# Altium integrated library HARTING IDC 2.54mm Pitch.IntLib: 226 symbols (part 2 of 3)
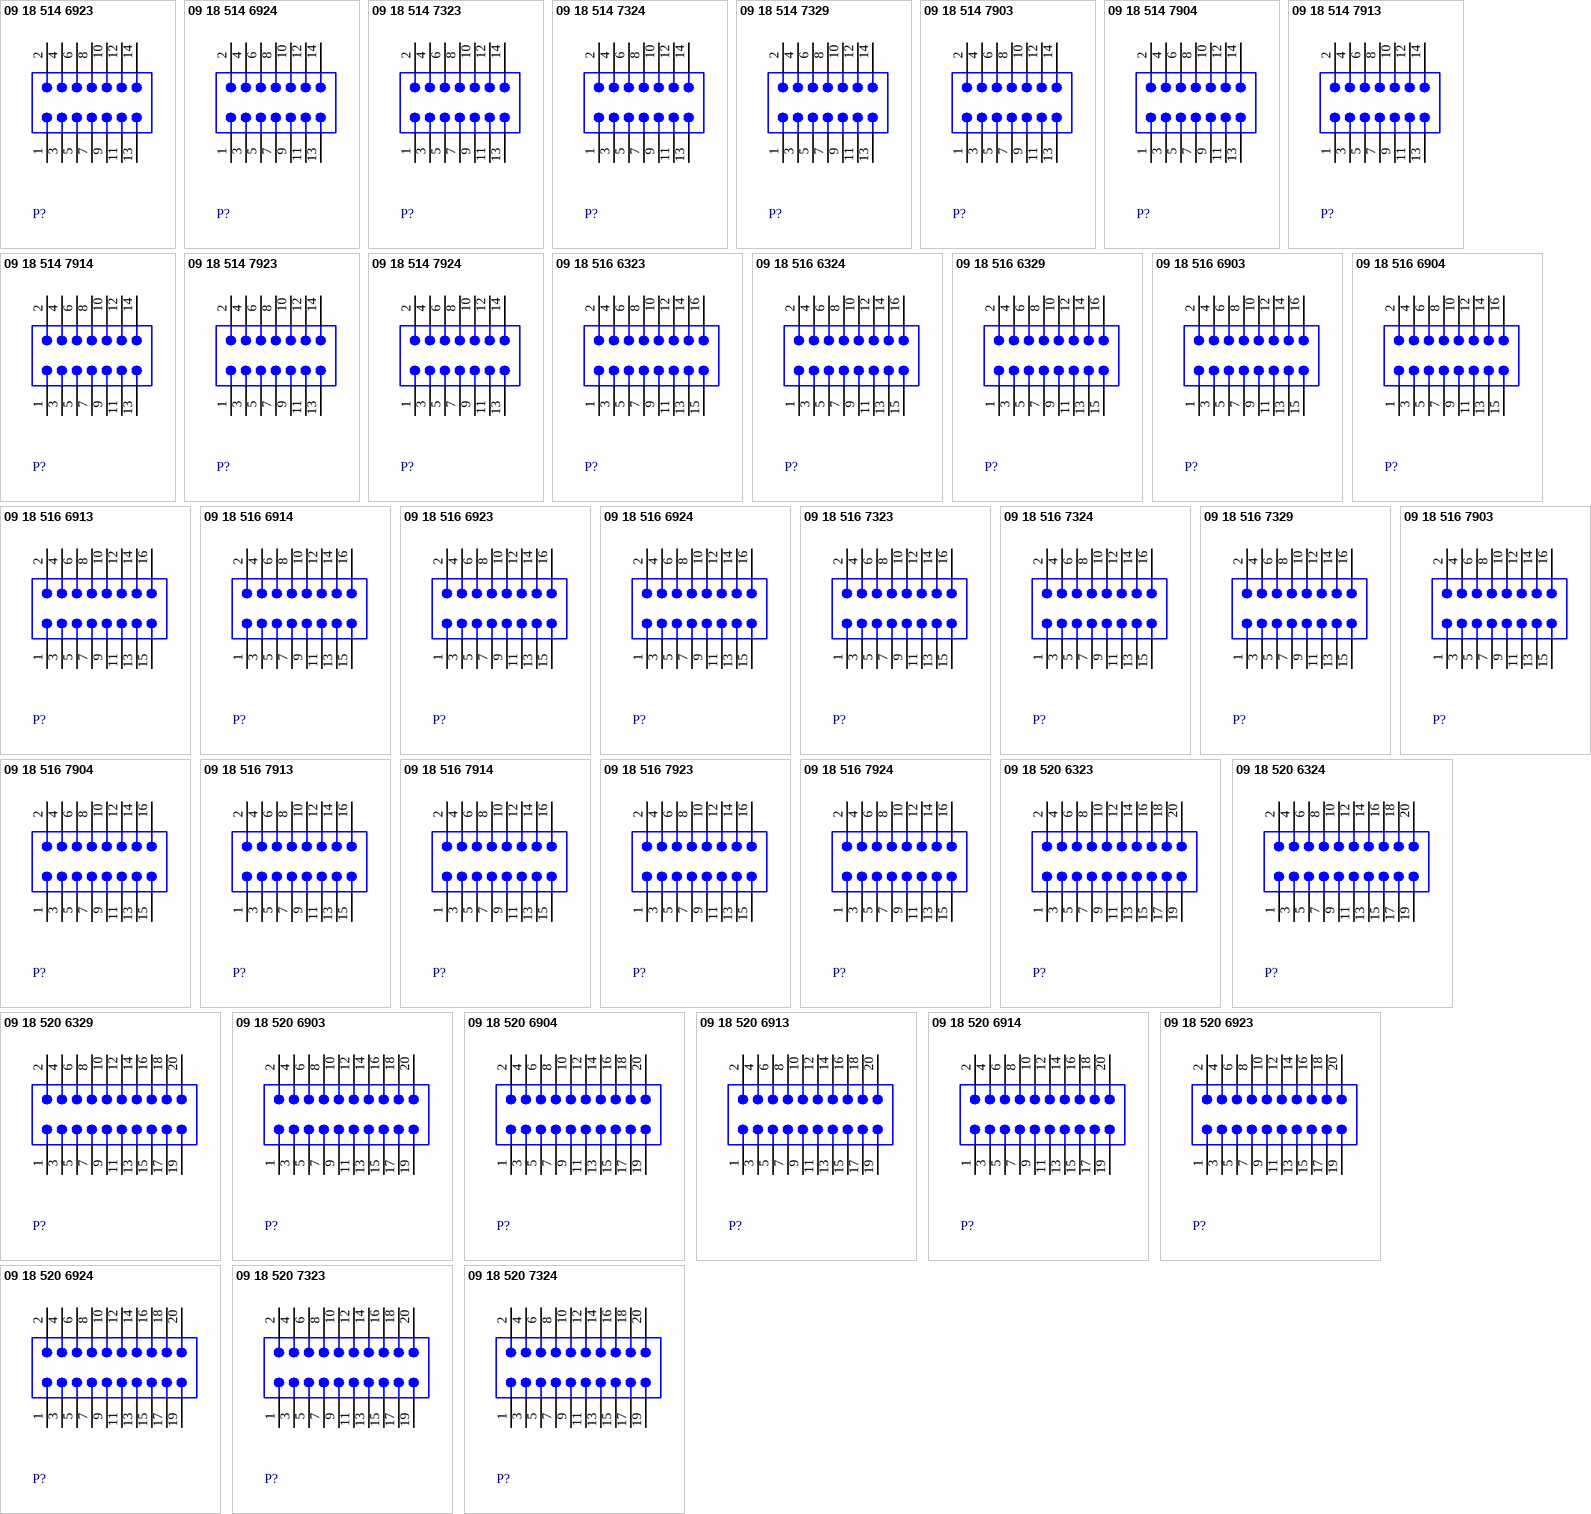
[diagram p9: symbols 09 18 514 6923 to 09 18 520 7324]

## 09 18 520 7323
designator P?
Flat Cable Connector (IDC), Low-Profile Male Header, Angled Solder Pin, 20 Contacts, Performance Level 3; PCB_Layout: Complies with manufacturer's recommendation.; DrillSize: Corresponds to nominal value.
footprint 918520x323 (Connector; IDC, Low Profile Male Header, Thru-Hole; 20 Position; Right Angle; Pitch 2.54 mm; Body 33.02 x 8.9 x 9.2 mm (LxWxH))
pins: 1, 2, 3, 4, 5, 6, 7, 8, 9, 10, 11, 12, 13, 14, 15, 16, 17, 18, 19, 20

## 09 18 520 7324
designator P?
Flat Cable Connector (IDC), Low-Profile Male Header, Straight Solder Pin, 20 Contacts, Performance Level 3; PCB_Layout: Complies with manufacturer's recommendation.; DrillSize: Corresponds to nominal value.
footprint 918520x324 (Connector; IDC, Low Profile Male Header, Thru-Hole; 20 Position; Vertical; Pitch 2.54 mm; Body 33.02 x 9.2 x 9.45 mm (LxWxH))
pins: 1, 2, 3, 4, 5, 6, 7, 8, 9, 10, 11, 12, 13, 14, 15, 16, 17, 18, 19, 20

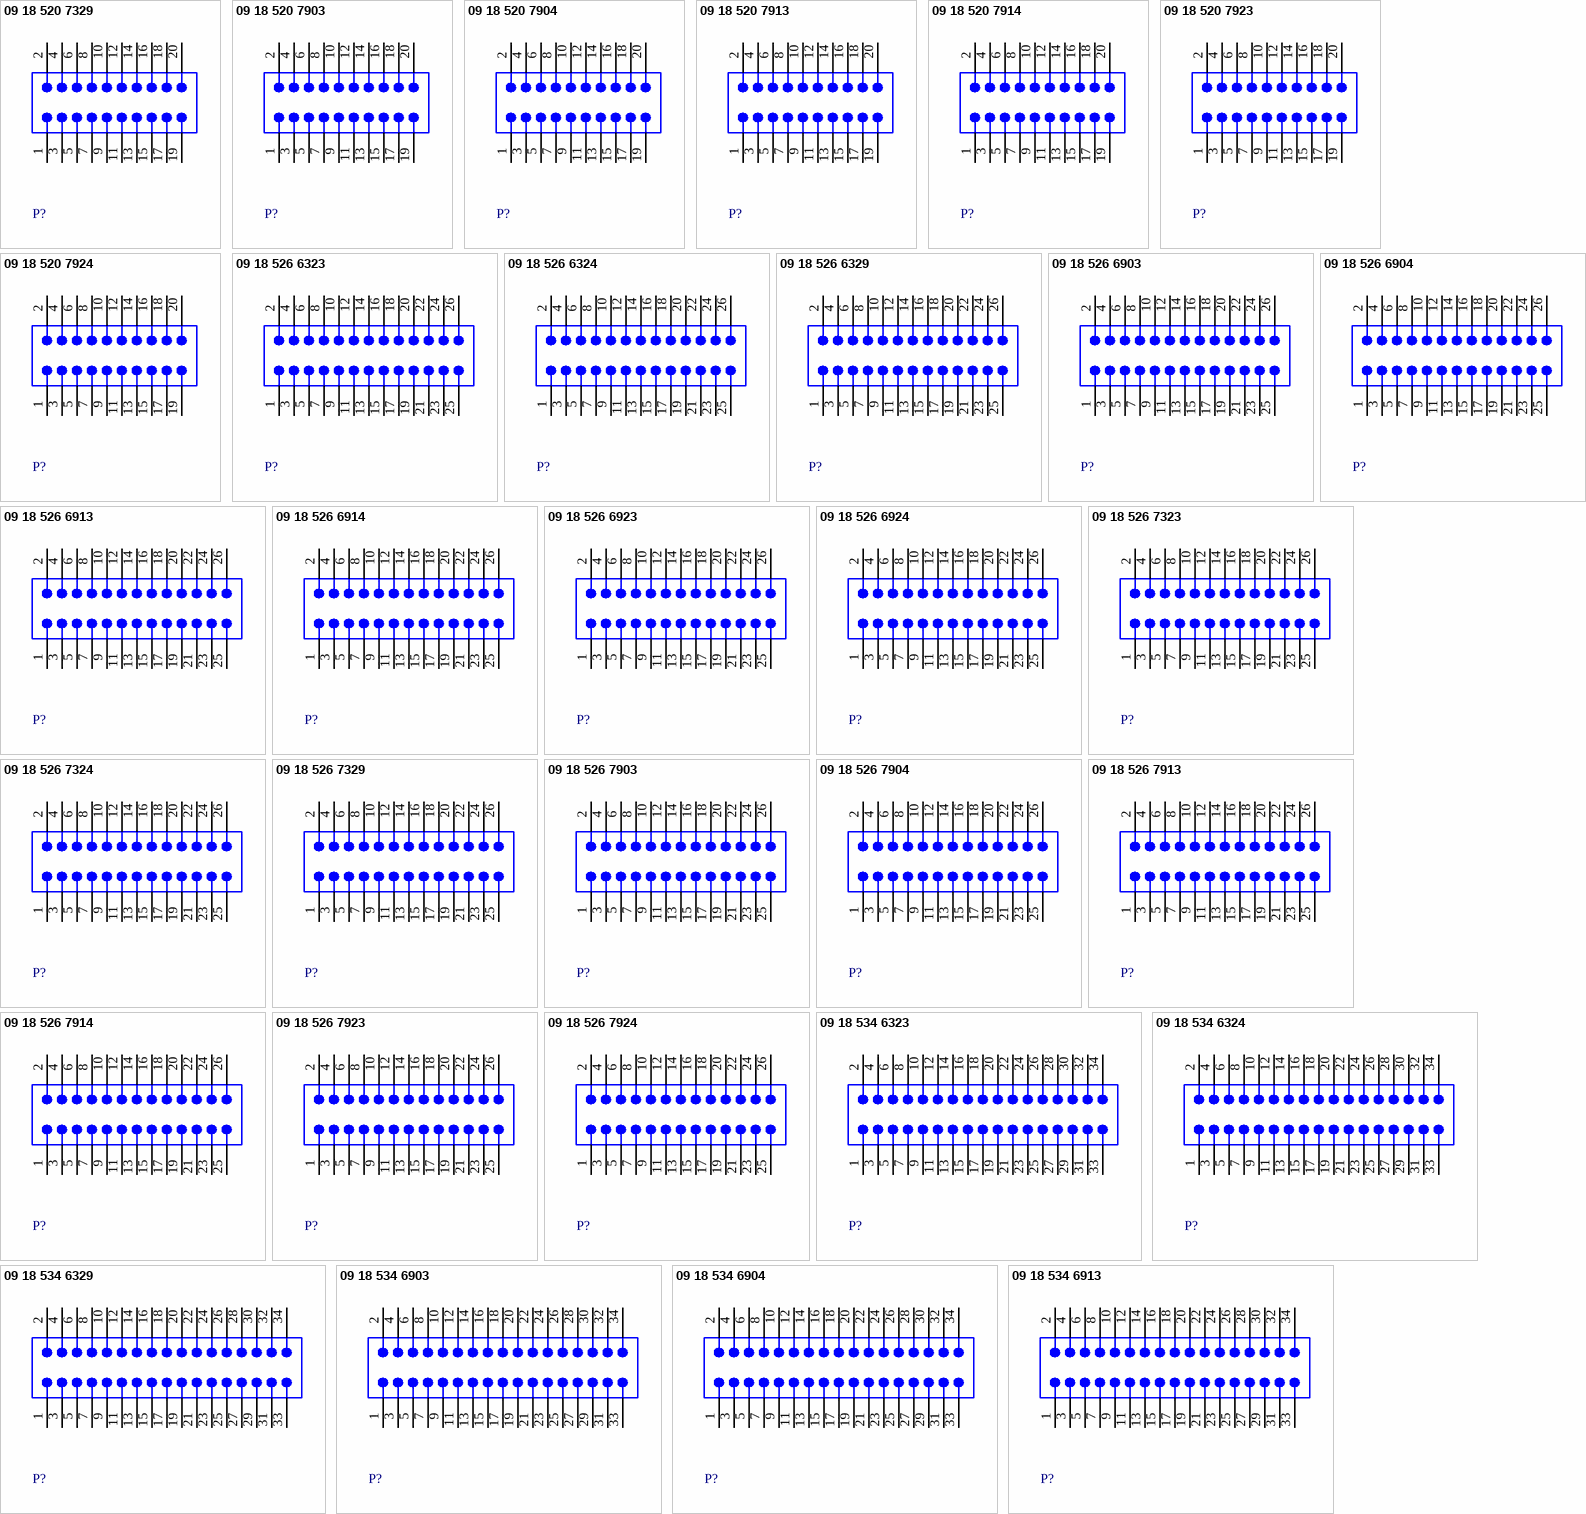
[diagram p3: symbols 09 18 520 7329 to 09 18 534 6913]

## 09 18 520 7329
designator P?
Flat Cable Connector (IDC), Standard Male Header, Straight Press-in Pin, 20 Contacts, Performance Level 3; PCB_Layout: Complies with manufacturer's recommendation.; DrillSize: Corresponds to nominal value.
footprint 918520x329 (Connector; IDC, Straight Press-in Pin, Thru-Hole; 20 Position; Vertical; Pitch 2.54 mm; Body 33.02 x 9.2 x 9.45 mm (LxWxH))
pins: 1, 2, 3, 4, 5, 6, 7, 8, 9, 10, 11, 12, 13, 14, 15, 16, 17, 18, 19, 20

## 09 18 520 7903
designator P?
Flat Cable Connector (IDC), Standard Male Header, Angled Solder Pin, 20 Contacts, Long Levers, Performance Level 3; PCB_Layout: Complies with manufacturer's recommendation.; DrillSize: Corresponds to nominal value.
footprint 918520x903 (Connector; IDC, Thru-Hole; 20 Position; Right Angle; Pitch 2.54 mm; Body 45.00 x 8.5 x 25.75 mm (LxHxW), Locking levers)
pins: 1, 2, 3, 4, 5, 6, 7, 8, 9, 10, 11, 12, 13, 14, 15, 16, 17, 18, 19, 20

## 09 18 520 7904
designator P?
Flat Cable Connector (IDC), Standard Male Header, Straight Solder Pin, 20 Contacts, Long Levers, Performance Level 3; PCB_Layout: Complies with manufacturer's recommendation.; DrillSize: Corresponds to nominal value.
footprint 918520x904 (Connector; IDC, Thru-Hole; 20 Position; Vertical; Pitch 2.54 mm; Body 45.00 x 8.5 x 25.75 mm (LxWxH), Locking levers)
pins: 1, 2, 3, 4, 5, 6, 7, 8, 9, 10, 11, 12, 13, 14, 15, 16, 17, 18, 19, 20

## 09 18 520 7913
designator P?
Flat Cable Connector (IDC), Standard Male Header, Angled Solder Pin, 20 Contacts, Short Levers, Performance Level 3; PCB_Layout: Complies with manufacturer's recommendation.; DrillSize: Corresponds to nominal value.
footprint 918520x913 (Connector; IDC, Thru-Hole; 20 Position; Right Angle; Pitch 2.54 mm; Body 45.00 x 8.5 x 23.30 mm (LxHxW), Locking levers)
pins: 1, 2, 3, 4, 5, 6, 7, 8, 9, 10, 11, 12, 13, 14, 15, 16, 17, 18, 19, 20

## 09 18 520 7914
designator P?
Flat Cable Connector (IDC), Standard Male Header, Straight Solder Pin, 20 Contacts, Short Levers, Performance Level 3; PCB_Layout: Complies with manufacturer's recommendation.; DrillSize: Corresponds to nominal value.
footprint 918520x914 (Connector; IDC, Thru-Hole; 20 Position; Vertical; Pitch 2.54 mm; Body 45.00 x 8.5 x 23.30 mm (LxWxH), Locking levers)
pins: 1, 2, 3, 4, 5, 6, 7, 8, 9, 10, 11, 12, 13, 14, 15, 16, 17, 18, 19, 20

## 09 18 520 7923
designator P?
Flat Cable Connector (IDC), Standard Male Header, Angled Solder Pin, 20 Contacts, Without Levers, Performance Level 3; PCB_Layout: Complies with manufacturer's recommendation.; DrillSize: Corresponds to nominal value.
footprint 918520x923 (Connector; IDC, Thru-Hole; 20 Position; Right Angle; Pitch 2.54 mm; Body 45.00 x 8.5 x 17.30 mm (LxHxW), Without locking levers)
pins: 1, 2, 3, 4, 5, 6, 7, 8, 9, 10, 11, 12, 13, 14, 15, 16, 17, 18, 19, 20

## 09 18 520 7924
designator P?
Flat Cable Connector (IDC), Standard Male Header, Straight Solder Pin, 20 Contacts, Without Levers, Performance Level 3; PCB_Layout: Complies with manufacturer's recommendation.; DrillSize: Corresponds to nominal value.
footprint 918520x924 (Connector; IDC, Thru-Hole; 20 Position; Vertical; Pitch 2.54 mm; Body 45.00 x 8.5 x 17.30 mm (LxWxH), Without locking levers)
pins: 1, 2, 3, 4, 5, 6, 7, 8, 9, 10, 11, 12, 13, 14, 15, 16, 17, 18, 19, 20

## 09 18 526 6323
designator P?
Flat Cable Connector (IDC), Low-Profile Male Header, Angled Solder Pin, 26 Contacts, Performance Level 2; PCB_Layout: Complies with manufacturer's recommendation.; DrillSize: Corresponds to nominal value.
footprint 918526x323 (Connector; IDC, Low Profile Male Header, Thru-Hole; 26 Position; Right Angle; Pitch 2.54 mm; Body 40.64 x 8.9 x 9.2 mm (LxWxH))
pins: 1, 2, 3, 4, 5, 6, 7, 8, 9, 10, 11, 12, 13, 14, 15, 16, 17, 18, 19, 20, 21, 22, 23, 24, 25, 26

## 09 18 526 6324
designator P?
Flat Cable Connector (IDC), Low-Profile Male Header, Straight Solder Pin, 26 Contacts, Performance Level 2; PCB_Layout: Complies with manufacturer's recommendation.; DrillSize: Corresponds to nominal value.
footprint 918526x324 (Connector; IDC, Low Profile Male Header, Thru-Hole; 26 Position; Vertical; Pitch 2.54 mm; Body 40.64 x 9.2 x 9.45 mm (LxWxH))
pins: 1, 2, 3, 4, 5, 6, 7, 8, 9, 10, 11, 12, 13, 14, 15, 16, 17, 18, 19, 20, 21, 22, 23, 24, 25, 26

## 09 18 526 6329
designator P?
Flat Cable Connector (IDC), Standard Male Header, Straight Press-in Pin, 26 Contacts, Performance Level 2; PCB_Layout: Complies with manufacturer's recommendation.; DrillSize: Corresponds to nominal value.
footprint 918526x329 (Connector; IDC, Straight Press-in Pin, Thru-Hole; 26 Position; Vertical; Pitch 2.54 mm; Body 40.64 x 9.2 x 9.45 mm (LxWxH))
pins: 1, 2, 3, 4, 5, 6, 7, 8, 9, 10, 11, 12, 13, 14, 15, 16, 17, 18, 19, 20, 21, 22, 23, 24, 25, 26

## 09 18 526 6903
designator P?
Flat Cable Connector (IDC), Standard Male Header, Angled Solder Pin, 26 Contacts, Long Levers, Performance Level 2; PCB_Layout: Complies with manufacturer's recommendation.; DrillSize: Corresponds to nominal value.
footprint 918526x903 (Connector; IDC, Thru-Hole; 26 Position; Right Angle; Pitch 2.54 mm; Body 52.60 x 8.5 x 25.75 mm (LxHxW), Locking levers)
pins: 1, 2, 3, 4, 5, 6, 7, 8, 9, 10, 11, 12, 13, 14, 15, 16, 17, 18, 19, 20, 21, 22, 23, 24, 25, 26

## 09 18 526 6904
designator P?
Flat Cable Connector (IDC), Standard Male Header, Straight Solder Pin, 26 Contacts, Long Levers, Performance Level 2; PCB_Layout: Complies with manufacturer's recommendation.; DrillSize: Corresponds to nominal value.
footprint 918526x904 (Connector; IDC, Thru-Hole; 26 Position; Vertical; Pitch 2.54 mm; Body 52.60 x 8.5 x 25.75 mm (LxWxH), Locking levers)
pins: 1, 2, 3, 4, 5, 6, 7, 8, 9, 10, 11, 12, 13, 14, 15, 16, 17, 18, 19, 20, 21, 22, 23, 24, 25, 26

## 09 18 526 6913
designator P?
Flat Cable Connector (IDC), Standard Male Header, Angled Solder Pin, 26 Contacts, Short Levers, Performance Level 2; PCB_Layout: Complies with manufacturer's recommendation.; DrillSize: Corresponds to nominal value.
footprint 918526x913 (Connector; IDC, Thru-Hole; 26 Position; Right Angle; Pitch 2.54 mm; Body 52.60 x 8.5 x 23.30 mm (LxHxW), Locking levers)
pins: 1, 2, 3, 4, 5, 6, 7, 8, 9, 10, 11, 12, 13, 14, 15, 16, 17, 18, 19, 20, 21, 22, 23, 24, 25, 26

## 09 18 526 6914
designator P?
Flat Cable Connector (IDC), Standard Male Header, Straight Solder Pin, 26 Contacts, Short Levers, Performance Level 2; PCB_Layout: Complies with manufacturer's recommendation.; DrillSize: Corresponds to nominal value.
footprint 918526x914 (Connector; IDC, Thru-Hole; 26 Position; Vertical; Pitch 2.54 mm; Body 52.60 x 8.5 x 23.30 mm (LxWxH), Locking levers)
pins: 1, 2, 3, 4, 5, 6, 7, 8, 9, 10, 11, 12, 13, 14, 15, 16, 17, 18, 19, 20, 21, 22, 23, 24, 25, 26

## 09 18 526 6923
designator P?
Flat Cable Connector (IDC), Standard Male Header, Angled Solder Pin, 26 Contacts, Without Levers, Performance Level 2; PCB_Layout: Complies with manufacturer's recommendation.; DrillSize: Corresponds to nominal value.
footprint 918526x923 (Connector; IDC, Thru-Hole; 26 Position; Right Angle; Pitch 2.54 mm; Body 52.60 x 8.5 x 17.30 mm (LxHxW), Without locking levers)
pins: 1, 2, 3, 4, 5, 6, 7, 8, 9, 10, 11, 12, 13, 14, 15, 16, 17, 18, 19, 20, 21, 22, 23, 24, 25, 26

## 09 18 526 6924
designator P?
Flat Cable Connector (IDC), Standard Male Header, Straight Solder Pin, 26 Contacts, Without Levers, Performance Level 2; PCB_Layout: Complies with manufacturer's recommendation.; DrillSize: Corresponds to nominal value.
footprint 918526x924 (Connector; IDC, Thru-Hole; 26 Position; Vertical; Pitch 2.54 mm; Body 52.60 x 8.5 x 17.30 mm (LxWxH), Without locking levers)
pins: 1, 2, 3, 4, 5, 6, 7, 8, 9, 10, 11, 12, 13, 14, 15, 16, 17, 18, 19, 20, 21, 22, 23, 24, 25, 26

## 09 18 526 7323
designator P?
Flat Cable Connector (IDC), Low-Profile Male Header, Angled Solder Pin, 26 Contacts, Performance Level 3; PCB_Layout: Complies with manufacturer's recommendation.; DrillSize: Corresponds to nominal value.
footprint 918526x323 (Connector; IDC, Low Profile Male Header, Thru-Hole; 26 Position; Right Angle; Pitch 2.54 mm; Body 40.64 x 8.9 x 9.2 mm (LxWxH))
pins: 1, 2, 3, 4, 5, 6, 7, 8, 9, 10, 11, 12, 13, 14, 15, 16, 17, 18, 19, 20, 21, 22, 23, 24, 25, 26

## 09 18 526 7324
designator P?
Flat Cable Connector (IDC), Low-Profile Male Header, Straight Solder Pin, 26 Contacts, Performance Level 3; PCB_Layout: Complies with manufacturer's recommendation.; DrillSize: Corresponds to nominal value.
footprint 918526x324 (Connector; IDC, Low Profile Male Header, Thru-Hole; 26 Position; Vertical; Pitch 2.54 mm; Body 40.64 x 9.2 x 9.45 mm (LxWxH))
pins: 1, 2, 3, 4, 5, 6, 7, 8, 9, 10, 11, 12, 13, 14, 15, 16, 17, 18, 19, 20, 21, 22, 23, 24, 25, 26

## 09 18 526 7329
designator P?
Flat Cable Connector (IDC), Standard Male Header, Straight Press-in Pin, 26 Contacts, Performance Level 3; PCB_Layout: Complies with manufacturer's recommendation.; DrillSize: Corresponds to nominal value.
footprint 918526x329 (Connector; IDC, Straight Press-in Pin, Thru-Hole; 26 Position; Vertical; Pitch 2.54 mm; Body 40.64 x 9.2 x 9.45 mm (LxWxH))
pins: 1, 2, 3, 4, 5, 6, 7, 8, 9, 10, 11, 12, 13, 14, 15, 16, 17, 18, 19, 20, 21, 22, 23, 24, 25, 26

## 09 18 526 7903
designator P?
Flat Cable Connector (IDC), Standard Male Header, Angled Solder Pin, 26 Contacts, Long Levers, Performance Level 3; PCB_Layout: Complies with manufacturer's recommendation.; DrillSize: Corresponds to nominal value.
footprint 918526x903 (Connector; IDC, Thru-Hole; 26 Position; Right Angle; Pitch 2.54 mm; Body 52.60 x 8.5 x 25.75 mm (LxHxW), Locking levers)
pins: 1, 2, 3, 4, 5, 6, 7, 8, 9, 10, 11, 12, 13, 14, 15, 16, 17, 18, 19, 20, 21, 22, 23, 24, 25, 26

## 09 18 526 7904
designator P?
Flat Cable Connector (IDC), Standard Male Header, Straight Solder Pin, 26 Contacts, Long Levers, Performance Level 3; PCB_Layout: Complies with manufacturer's recommendation.; DrillSize: Corresponds to nominal value.
footprint 918526x904 (Connector; IDC, Thru-Hole; 26 Position; Vertical; Pitch 2.54 mm; Body 52.60 x 8.5 x 25.75 mm (LxWxH), Locking levers)
pins: 1, 2, 3, 4, 5, 6, 7, 8, 9, 10, 11, 12, 13, 14, 15, 16, 17, 18, 19, 20, 21, 22, 23, 24, 25, 26

## 09 18 526 7913
designator P?
Flat Cable Connector (IDC), Standard Male Header, Angled Solder Pin, 26 Contacts, Short Levers, Performance Level 3; PCB_Layout: Complies with manufacturer's recommendation.; DrillSize: Corresponds to nominal value.
footprint 918526x913 (Connector; IDC, Thru-Hole; 26 Position; Right Angle; Pitch 2.54 mm; Body 52.60 x 8.5 x 23.30 mm (LxHxW), Locking levers)
pins: 1, 2, 3, 4, 5, 6, 7, 8, 9, 10, 11, 12, 13, 14, 15, 16, 17, 18, 19, 20, 21, 22, 23, 24, 25, 26

## 09 18 526 7914
designator P?
Flat Cable Connector (IDC), Standard Male Header, Straight Solder Pin, 26 Contacts, Short Levers, Performance Level 3; PCB_Layout: Complies with manufacturer's recommendation.; DrillSize: Corresponds to nominal value.
footprint 918526x914 (Connector; IDC, Thru-Hole; 26 Position; Vertical; Pitch 2.54 mm; Body 52.60 x 8.5 x 23.30 mm (LxWxH), Locking levers)
pins: 1, 2, 3, 4, 5, 6, 7, 8, 9, 10, 11, 12, 13, 14, 15, 16, 17, 18, 19, 20, 21, 22, 23, 24, 25, 26

## 09 18 526 7923
designator P?
Flat Cable Connector (IDC), Standard Male Header, Angled Solder Pin, 26 Contacts, Without Levers, Performance Level 3; PCB_Layout: Complies with manufacturer's recommendation.; DrillSize: Corresponds to nominal value.
footprint 918526x923 (Connector; IDC, Thru-Hole; 26 Position; Right Angle; Pitch 2.54 mm; Body 52.60 x 8.5 x 17.30 mm (LxHxW), Without locking levers)
pins: 1, 2, 3, 4, 5, 6, 7, 8, 9, 10, 11, 12, 13, 14, 15, 16, 17, 18, 19, 20, 21, 22, 23, 24, 25, 26

## 09 18 526 7924
designator P?
Flat Cable Connector (IDC), Standard Male Header, Straight Solder Pin, 26 Contacts, Without Levers, Performance Level 3; PCB_Layout: Complies with manufacturer's recommendation.; DrillSize: Corresponds to nominal value.
footprint 918526x924 (Connector; IDC, Thru-Hole; 26 Position; Vertical; Pitch 2.54 mm; Body 52.60 x 8.5 x 17.30 mm (LxWxH), Without locking levers)
pins: 1, 2, 3, 4, 5, 6, 7, 8, 9, 10, 11, 12, 13, 14, 15, 16, 17, 18, 19, 20, 21, 22, 23, 24, 25, 26

## 09 18 534 6323
designator P?
Flat Cable Connector (IDC), Low-Profile Male Header, Angled Solder Pin, 34 Contacts, Performance Level 2; PCB_Layout: Complies with manufacturer's recommendation.; DrillSize: Corresponds to nominal value.
footprint 918534x323 (Connector; IDC, Low Profile Male Header, Thru-Hole; 34 Position; Right Angle; Pitch 2.54 mm; Body 50.80 x 8.9 x 9.2 mm (LxWxH))
pins: 1, 2, 3, 4, 5, 6, 7, 8, 9, 10, 11, 12, 13, 14, 15, 16, 17, 18, 19, 20, 21, 22, 23, 24, 25, 26, 27, 28, 29, 30, 31, 32, 33, 34

## 09 18 534 6324
designator P?
Flat Cable Connector (IDC), Low-Profile Male Header, Straight Solder Pin, 34 Contacts, Performance Level 2; PCB_Layout: Complies with manufacturer's recommendation.; DrillSize: Corresponds to nominal value.
footprint 918534x324 (Connector; IDC, Low Profile Male Header, Thru-Hole; 34 Position; Vertical; Pitch 2.54 mm; Body 50.80 x 9.2 x 9.45 mm (LxWxH))
pins: 1, 2, 3, 4, 5, 6, 7, 8, 9, 10, 11, 12, 13, 14, 15, 16, 17, 18, 19, 20, 21, 22, 23, 24, 25, 26, 27, 28, 29, 30, 31, 32, 33, 34

## 09 18 534 6329
designator P?
Flat Cable Connector (IDC), Standard Male Header, Straight Press-in Pin, 34 Contacts, Performance Level 2; PCB_Layout: Complies with manufacturer's recommendation.; DrillSize: Corresponds to nominal value.
footprint 918534x329 (Connector; IDC, Straight Press-in Pin, Thru-Hole; 34 Position; Vertical; Pitch 2.54 mm; Body 50.80 x 9.2 x 9.45 mm (LxWxH))
pins: 1, 2, 3, 4, 5, 6, 7, 8, 9, 10, 11, 12, 13, 14, 15, 16, 17, 18, 19, 20, 21, 22, 23, 24, 25, 26, 27, 28, 29, 30, 31, 32, 33, 34

## 09 18 534 6903
designator P?
Flat Cable Connector (IDC), Standard Male Header, Angled Solder Pin, 34 Contacts, Long Levers, Performance Level 2; PCB_Layout: Complies with manufacturer's recommendation.; DrillSize: Corresponds to nominal value.
footprint 918534x903 (Connector; IDC, Thru-Hole; 34 Position; Right Angle; Pitch 2.54 mm; Body 62.80 x 8.5 x 25.75 mm (LxHxW), Locking levers)
pins: 1, 2, 3, 4, 5, 6, 7, 8, 9, 10, 11, 12, 13, 14, 15, 16, 17, 18, 19, 20, 21, 22, 23, 24, 25, 26, 27, 28, 29, 30, 31, 32, 33, 34

## 09 18 534 6904
designator P?
Flat Cable Connector (IDC), Standard Male Header, Straight Solder Pin, 34 Contacts, Long Levers, Performance Level 2; PCB_Layout: Complies with manufacturer's recommendation.; DrillSize: Corresponds to nominal value.
footprint 918534x904 (Connector; IDC, Thru-Hole; 34 Position; Vertical; Pitch 2.54 mm; Body 62.80 x 8.5 x 25.75 mm (LxWxH), Locking levers)
pins: 1, 2, 3, 4, 5, 6, 7, 8, 9, 10, 11, 12, 13, 14, 15, 16, 17, 18, 19, 20, 21, 22, 23, 24, 25, 26, 27, 28, 29, 30, 31, 32, 33, 34

## 09 18 534 6913
designator P?
Flat Cable Connector (IDC), Standard Male Header, Angled Solder Pin, 34 Contacts, Short Levers, Performance Level 2; PCB_Layout: Complies with manufacturer's recommendation.; DrillSize: Corresponds to nominal value.
footprint 918534x913 (Connector; IDC, Thru-Hole; 34 Position; Right Angle; Pitch 2.54 mm; Body 62.80 x 8.5 x 23.30 mm (LxHxW), Locking levers)
pins: 1, 2, 3, 4, 5, 6, 7, 8, 9, 10, 11, 12, 13, 14, 15, 16, 17, 18, 19, 20, 21, 22, 23, 24, 25, 26, 27, 28, 29, 30, 31, 32, 33, 34

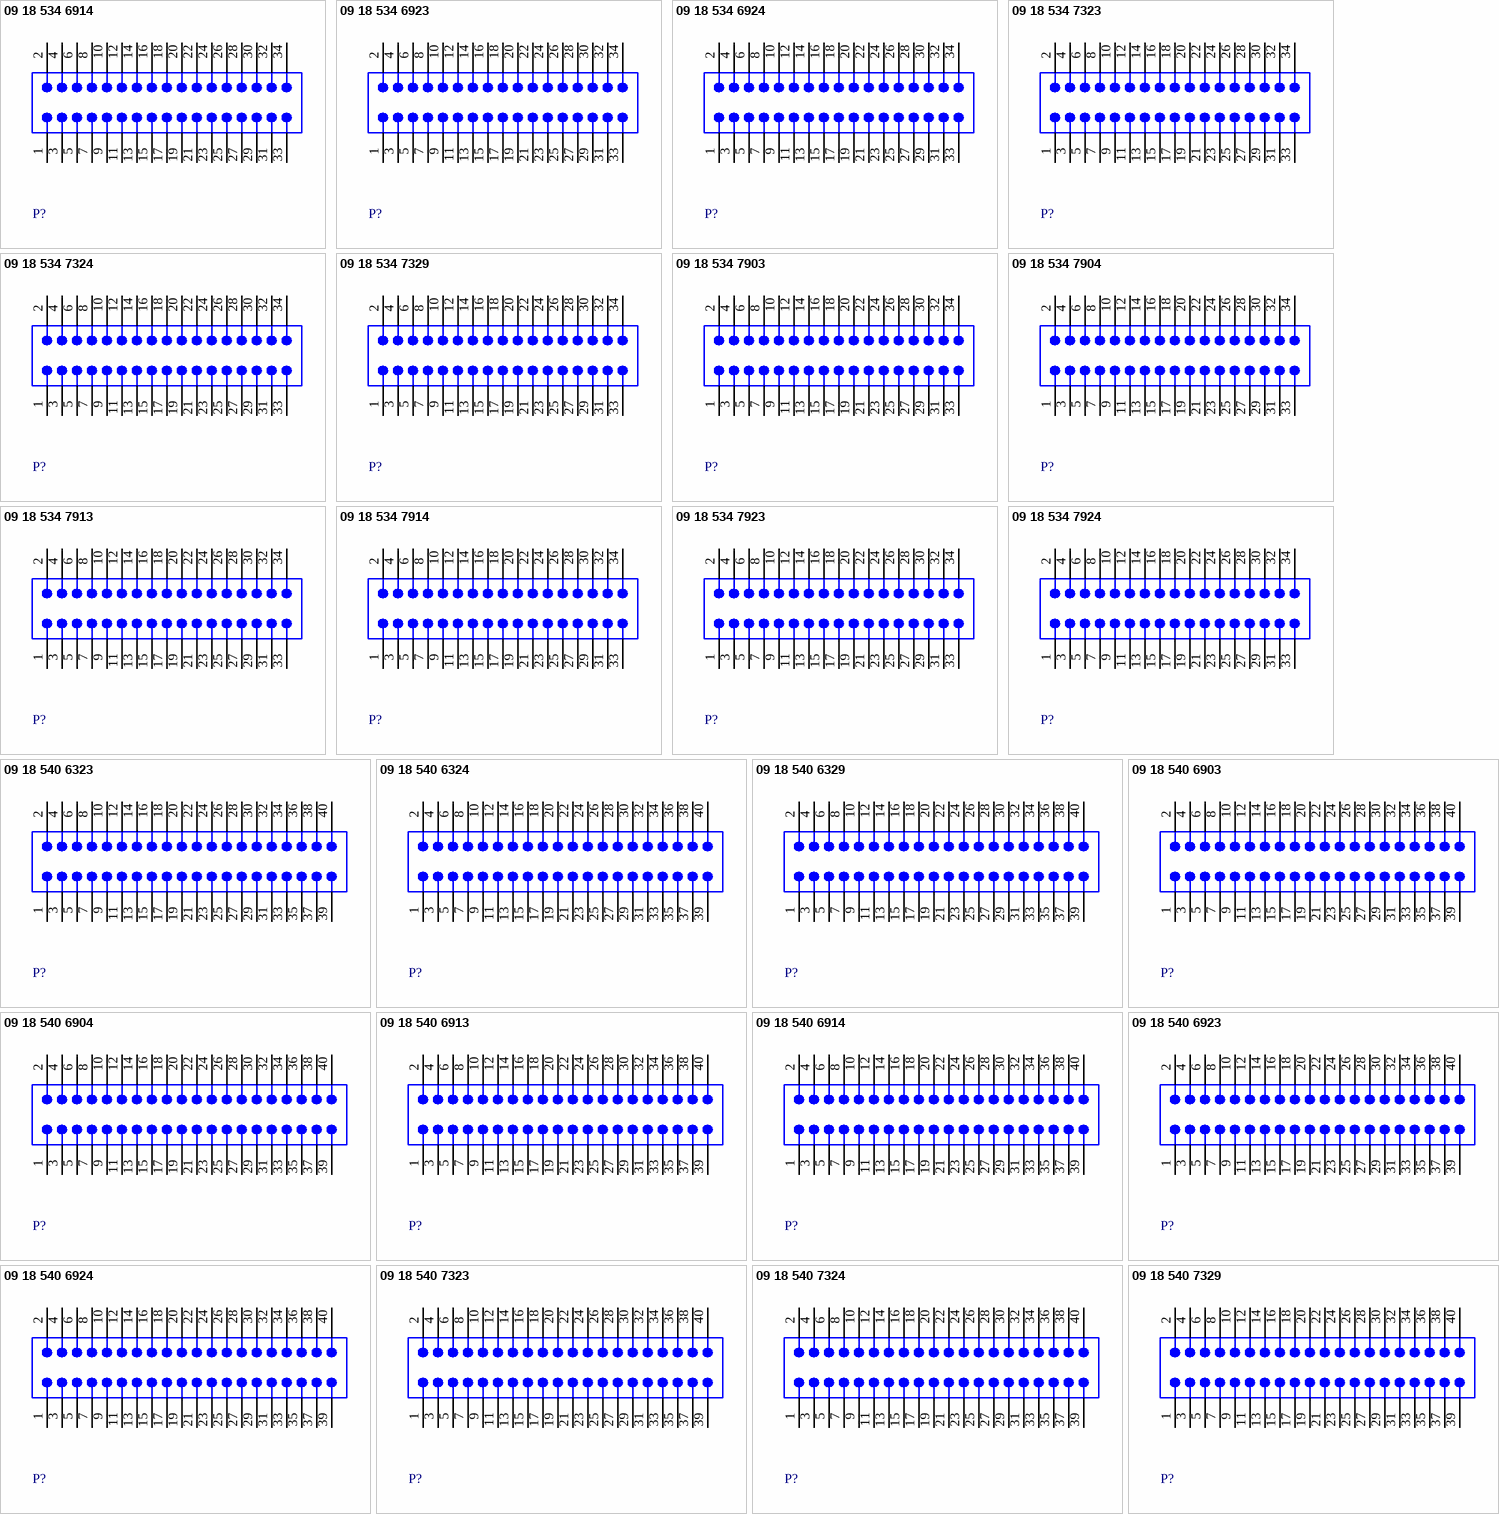
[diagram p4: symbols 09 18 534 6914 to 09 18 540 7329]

## 09 18 534 6914
designator P?
Flat Cable Connector (IDC), Standard Male Header, Straight Solder Pin, 34 Contacts, Short Levers, Performance Level 2; PCB_Layout: Complies with manufacturer's recommendation.; DrillSize: Corresponds to nominal value.
footprint 918534x914 (Connector; IDC, Thru-Hole; 34 Position; Vertical; Pitch 2.54 mm; Body 62.80 x 8.5 x 23.30 mm (LxWxH), Locking levers)
pins: 1, 2, 3, 4, 5, 6, 7, 8, 9, 10, 11, 12, 13, 14, 15, 16, 17, 18, 19, 20, 21, 22, 23, 24, 25, 26, 27, 28, 29, 30, 31, 32, 33, 34

## 09 18 534 6923
designator P?
Flat Cable Connector (IDC), Standard Male Header, Angled Solder Pin, 34 Contacts, Without Levers, Performance Level 2; PCB_Layout: Complies with manufacturer's recommendation.; DrillSize: Corresponds to nominal value.
footprint 918534x923 (Connector; IDC, Thru-Hole; 34 Position; Right Angle; Pitch 2.54 mm; Body 62.80 x 8.5 x 17.30 mm (LxHxW), Without locking levers)
pins: 1, 2, 3, 4, 5, 6, 7, 8, 9, 10, 11, 12, 13, 14, 15, 16, 17, 18, 19, 20, 21, 22, 23, 24, 25, 26, 27, 28, 29, 30, 31, 32, 33, 34

## 09 18 534 6924
designator P?
Flat Cable Connector (IDC), Standard Male Header, Straight Solder Pin, 34 Contacts, Without Levers, Performance Level 2; PCB_Layout: Complies with manufacturer's recommendation.; DrillSize: Corresponds to nominal value.
footprint 918534x924 (Connector; IDC, Thru-Hole; 34 Position; Vertical; Pitch 2.54 mm; Body 62.80 x 8.5 x 17.30 mm (LxWxH), Without locking levers)
pins: 1, 2, 3, 4, 5, 6, 7, 8, 9, 10, 11, 12, 13, 14, 15, 16, 17, 18, 19, 20, 21, 22, 23, 24, 25, 26, 27, 28, 29, 30, 31, 32, 33, 34

## 09 18 534 7323
designator P?
Flat Cable Connector (IDC), Low-Profile Male Header, Angled Solder Pin, 34 Contacts, Performance Level 3; PCB_Layout: Complies with manufacturer's recommendation.; DrillSize: Corresponds to nominal value.
footprint 918534x323 (Connector; IDC, Low Profile Male Header, Thru-Hole; 34 Position; Right Angle; Pitch 2.54 mm; Body 50.80 x 8.9 x 9.2 mm (LxWxH))
pins: 1, 2, 3, 4, 5, 6, 7, 8, 9, 10, 11, 12, 13, 14, 15, 16, 17, 18, 19, 20, 21, 22, 23, 24, 25, 26, 27, 28, 29, 30, 31, 32, 33, 34

## 09 18 534 7324
designator P?
Flat Cable Connector (IDC), Low-Profile Male Header, Straight Solder Pin, 34 Contacts, Performance Level 3; PCB_Layout: Complies with manufacturer's recommendation.; DrillSize: Corresponds to nominal value.
footprint 918534x324 (Connector; IDC, Low Profile Male Header, Thru-Hole; 34 Position; Vertical; Pitch 2.54 mm; Body 50.80 x 9.2 x 9.45 mm (LxWxH))
pins: 1, 2, 3, 4, 5, 6, 7, 8, 9, 10, 11, 12, 13, 14, 15, 16, 17, 18, 19, 20, 21, 22, 23, 24, 25, 26, 27, 28, 29, 30, 31, 32, 33, 34

## 09 18 534 7329
designator P?
Flat Cable Connector (IDC), Standard Male Header, Straight Press-in Pin, 34 Contacts, Performance Level 3; PCB_Layout: Complies with manufacturer's recommendation.; DrillSize: Corresponds to nominal value.
footprint 918534x329 (Connector; IDC, Straight Press-in Pin, Thru-Hole; 34 Position; Vertical; Pitch 2.54 mm; Body 50.80 x 9.2 x 9.45 mm (LxWxH))
pins: 1, 2, 3, 4, 5, 6, 7, 8, 9, 10, 11, 12, 13, 14, 15, 16, 17, 18, 19, 20, 21, 22, 23, 24, 25, 26, 27, 28, 29, 30, 31, 32, 33, 34

## 09 18 534 7903
designator P?
Flat Cable Connector (IDC), Standard Male Header, Angled Solder Pin, 34 Contacts, Long Levers, Performance Level 3; PCB_Layout: Complies with manufacturer's recommendation.; DrillSize: Corresponds to nominal value.
footprint 918534x903 (Connector; IDC, Thru-Hole; 34 Position; Right Angle; Pitch 2.54 mm; Body 62.80 x 8.5 x 25.75 mm (LxHxW), Locking levers)
pins: 1, 2, 3, 4, 5, 6, 7, 8, 9, 10, 11, 12, 13, 14, 15, 16, 17, 18, 19, 20, 21, 22, 23, 24, 25, 26, 27, 28, 29, 30, 31, 32, 33, 34

## 09 18 534 7904
designator P?
Flat Cable Connector (IDC), Standard Male Header, Straight Solder Pin, 34 Contacts, Long Levers, Performance Level 3; PCB_Layout: Complies with manufacturer's recommendation.; DrillSize: Corresponds to nominal value.
footprint 918534x904 (Connector; IDC, Thru-Hole; 34 Position; Vertical; Pitch 2.54 mm; Body 62.80 x 8.5 x 25.75 mm (LxWxH), Locking levers)
pins: 1, 2, 3, 4, 5, 6, 7, 8, 9, 10, 11, 12, 13, 14, 15, 16, 17, 18, 19, 20, 21, 22, 23, 24, 25, 26, 27, 28, 29, 30, 31, 32, 33, 34

## 09 18 534 7913
designator P?
Flat Cable Connector (IDC), Standard Male Header, Angled Solder Pin, 34 Contacts, Short Levers, Performance Level 3; PCB_Layout: Complies with manufacturer's recommendation.; DrillSize: Corresponds to nominal value.
footprint 918534x913 (Connector; IDC, Thru-Hole; 34 Position; Right Angle; Pitch 2.54 mm; Body 62.80 x 8.5 x 23.30 mm (LxHxW), Locking levers)
pins: 1, 2, 3, 4, 5, 6, 7, 8, 9, 10, 11, 12, 13, 14, 15, 16, 17, 18, 19, 20, 21, 22, 23, 24, 25, 26, 27, 28, 29, 30, 31, 32, 33, 34

## 09 18 534 7914
designator P?
Flat Cable Connector (IDC), Standard Male Header, Straight Solder Pin, 34 Contacts, Short Levers, Performance Level 3; PCB_Layout: Complies with manufacturer's recommendation.; DrillSize: Corresponds to nominal value.
footprint 918534x914 (Connector; IDC, Thru-Hole; 34 Position; Vertical; Pitch 2.54 mm; Body 62.80 x 8.5 x 23.30 mm (LxWxH), Locking levers)
pins: 1, 2, 3, 4, 5, 6, 7, 8, 9, 10, 11, 12, 13, 14, 15, 16, 17, 18, 19, 20, 21, 22, 23, 24, 25, 26, 27, 28, 29, 30, 31, 32, 33, 34

## 09 18 534 7923
designator P?
Flat Cable Connector (IDC), Standard Male Header, Angled Solder Pin, 34 Contacts, Without Levers, Performance Level 3; PCB_Layout: Complies with manufacturer's recommendation.; DrillSize: Corresponds to nominal value.
footprint 918534x923 (Connector; IDC, Thru-Hole; 34 Position; Right Angle; Pitch 2.54 mm; Body 62.80 x 8.5 x 17.30 mm (LxHxW), Without locking levers)
pins: 1, 2, 3, 4, 5, 6, 7, 8, 9, 10, 11, 12, 13, 14, 15, 16, 17, 18, 19, 20, 21, 22, 23, 24, 25, 26, 27, 28, 29, 30, 31, 32, 33, 34

## 09 18 534 7924
designator P?
Flat Cable Connector (IDC), Standard Male Header, Straight Solder Pin, 34 Contacts, Without Levers, Performance Level 3; PCB_Layout: Complies with manufacturer's recommendation.; DrillSize: Corresponds to nominal value.
footprint 918534x924 (Connector; IDC, Thru-Hole; 34 Position; Vertical; Pitch 2.54 mm; Body 62.80 x 8.5 x 17.30 mm (LxWxH), Without locking levers)
pins: 1, 2, 3, 4, 5, 6, 7, 8, 9, 10, 11, 12, 13, 14, 15, 16, 17, 18, 19, 20, 21, 22, 23, 24, 25, 26, 27, 28, 29, 30, 31, 32, 33, 34

## 09 18 540 6323
designator P?
Flat Cable Connector (IDC), Low-Profile Male Header, Angled Solder Pin, 40 Contacts, Performance Level 2; PCB_Layout: Complies with manufacturer's recommendation.; DrillSize: Corresponds to nominal value.
footprint 918540x323 (Connector; IDC, Low Profile Male Header, Thru-Hole; 40 Position; Right Angle; Pitch 2.54 mm; Body 58.42 x 8.9 x 9.2 mm (LxWxH))
pins: 1, 2, 3, 4, 5, 6, 7, 8, 9, 10, 11, 12, 13, 14, 15, 16, 17, 18, 19, 20, 21, 22, 23, 24, 25, 26, 27, 28, 29, 30, 31, 32, 33, 34, 35, 36, 37, 38, 39, 40

## 09 18 540 6324
designator P?
Flat Cable Connector (IDC), Low-Profile Male Header, Straight Solder Pin, 40 Contacts, Performance Level 2; PCB_Layout: Complies with manufacturer's recommendation.; DrillSize: Corresponds to nominal value.
footprint 918540x324 (Connector; IDC, Low Profile Male Header, Thru-Hole; 40 Position; Vertical; Pitch 2.54 mm; Body 58.42 x 9.2 x 9.45 mm (LxWxH))
pins: 1, 2, 3, 4, 5, 6, 7, 8, 9, 10, 11, 12, 13, 14, 15, 16, 17, 18, 19, 20, 21, 22, 23, 24, 25, 26, 27, 28, 29, 30, 31, 32, 33, 34, 35, 36, 37, 38, 39, 40

## 09 18 540 6329
designator P?
Flat Cable Connector (IDC), Standard Male Header, Straight Press-in Pin, 40 Contacts, Performance Level 2; PCB_Layout: Complies with manufacturer's recommendation.; DrillSize: Corresponds to nominal value.
footprint 918540x329 (Connector; IDC, Straight Press-in Pin, Thru-Hole; 40 Position; Vertical; Pitch 2.54 mm; Body 58.42 x 9.2 x 9.45 mm (LxWxH))
pins: 1, 2, 3, 4, 5, 6, 7, 8, 9, 10, 11, 12, 13, 14, 15, 16, 17, 18, 19, 20, 21, 22, 23, 24, 25, 26, 27, 28, 29, 30, 31, 32, 33, 34, 35, 36, 37, 38, 39, 40

## 09 18 540 6903
designator P?
Flat Cable Connector (IDC), Standard Male Header, Angled Solder Pin, 40 Contacts, Long Levers, Performance Level 2; PCB_Layout: Complies with manufacturer's recommendation.; DrillSize: Corresponds to nominal value.
footprint 918540x903 (Connector; IDC, Thru-Hole; 40 Position; Right Angle; Pitch 2.54 mm; Body 70.40 x 8.5 x 25.75 mm (LxHxW), Locking levers)
pins: 1, 2, 3, 4, 5, 6, 7, 8, 9, 10, 11, 12, 13, 14, 15, 16, 17, 18, 19, 20, 21, 22, 23, 24, 25, 26, 27, 28, 29, 30, 31, 32, 33, 34, 35, 36, 37, 38, 39, 40

## 09 18 540 6904
designator P?
Flat Cable Connector (IDC), Standard Male Header, Straight Solder Pin, 40 Contacts, Long Levers, Performance Level 2; PCB_Layout: Complies with manufacturer's recommendation.; DrillSize: Corresponds to nominal value.
footprint 918540x904 (Connector; IDC, Thru-Hole; 40 Position; Vertical; Pitch 2.54 mm; Body 70.40 x 8.5 x 25.75 mm (LxWxH), Locking levers)
pins: 1, 2, 3, 4, 5, 6, 7, 8, 9, 10, 11, 12, 13, 14, 15, 16, 17, 18, 19, 20, 21, 22, 23, 24, 25, 26, 27, 28, 29, 30, 31, 32, 33, 34, 35, 36, 37, 38, 39, 40

## 09 18 540 6913
designator P?
Flat Cable Connector (IDC), Standard Male Header, Angled Solder Pin, 40 Contacts, Short Levers, Performance Level 2; PCB_Layout: Complies with manufacturer's recommendation.; DrillSize: Corresponds to nominal value.
footprint 918540x913 (Connector; IDC, Thru-Hole; 40 Position; Right Angle; Pitch 2.54 mm; Body 70.40 x 8.5 x 23.30 mm (LxHxW), Locking levers)
pins: 1, 2, 3, 4, 5, 6, 7, 8, 9, 10, 11, 12, 13, 14, 15, 16, 17, 18, 19, 20, 21, 22, 23, 24, 25, 26, 27, 28, 29, 30, 31, 32, 33, 34, 35, 36, 37, 38, 39, 40

## 09 18 540 6914
designator P?
Flat Cable Connector (IDC), Standard Male Header, Straight Solder Pin, 40 Contacts, Short Levers, Performance Level 2; PCB_Layout: Complies with manufacturer's recommendation.; DrillSize: Corresponds to nominal value.
footprint 918540x914 (Connector; IDC, Thru-Hole; 40 Position; Vertical; Pitch 2.54 mm; Body 70.40 x 8.5 x 23.30 mm (LxWxH), Locking levers)
pins: 1, 2, 3, 4, 5, 6, 7, 8, 9, 10, 11, 12, 13, 14, 15, 16, 17, 18, 19, 20, 21, 22, 23, 24, 25, 26, 27, 28, 29, 30, 31, 32, 33, 34, 35, 36, 37, 38, 39, 40

## 09 18 540 6923
designator P?
Flat Cable Connector (IDC), Standard Male Header, Angled Solder Pin, 40 Contacts, Without Levers, Performance Level 2; PCB_Layout: Complies with manufacturer's recommendation.; DrillSize: Corresponds to nominal value.
footprint 918540x923 (Connector; IDC, Thru-Hole; 40 Position; Right Angle; Pitch 2.54 mm; Body 70.40 x 8.5 x 17.30 mm (LxHxW), Without locking levers)
pins: 1, 2, 3, 4, 5, 6, 7, 8, 9, 10, 11, 12, 13, 14, 15, 16, 17, 18, 19, 20, 21, 22, 23, 24, 25, 26, 27, 28, 29, 30, 31, 32, 33, 34, 35, 36, 37, 38, 39, 40

## 09 18 540 6924
designator P?
Flat Cable Connector (IDC), Standard Male Header, Straight Solder Pin, 40 Contacts, Without Levers, Performance Level 2; PCB_Layout: Complies with manufacturer's recommendation.; DrillSize: Corresponds to nominal value.
footprint 918540x924 (Connector; IDC, Thru-Hole; 40 Position; Vertical; Pitch 2.54 mm; Body 70.40 x 8.5 x 17.30 mm (LxWxH), Without locking levers)
pins: 1, 2, 3, 4, 5, 6, 7, 8, 9, 10, 11, 12, 13, 14, 15, 16, 17, 18, 19, 20, 21, 22, 23, 24, 25, 26, 27, 28, 29, 30, 31, 32, 33, 34, 35, 36, 37, 38, 39, 40

## 09 18 540 7323
designator P?
Flat Cable Connector (IDC), Low-Profile Male Header, Angled Solder Pin, 40 Contacts, Performance Level 3; PCB_Layout: Complies with manufacturer's recommendation.; DrillSize: Corresponds to nominal value.
footprint 918540x323 (Connector; IDC, Low Profile Male Header, Thru-Hole; 40 Position; Right Angle; Pitch 2.54 mm; Body 58.42 x 8.9 x 9.2 mm (LxWxH))
pins: 1, 2, 3, 4, 5, 6, 7, 8, 9, 10, 11, 12, 13, 14, 15, 16, 17, 18, 19, 20, 21, 22, 23, 24, 25, 26, 27, 28, 29, 30, 31, 32, 33, 34, 35, 36, 37, 38, 39, 40

## 09 18 540 7324
designator P?
Flat Cable Connector (IDC), Low-Profile Male Header, Straight Solder Pin, 40 Contacts, Performance Level 3; PCB_Layout: Complies with manufacturer's recommendation.; DrillSize: Corresponds to nominal value.
footprint 918540x324 (Connector; IDC, Low Profile Male Header, Thru-Hole; 40 Position; Vertical; Pitch 2.54 mm; Body 58.42 x 9.2 x 9.45 mm (LxWxH))
pins: 1, 2, 3, 4, 5, 6, 7, 8, 9, 10, 11, 12, 13, 14, 15, 16, 17, 18, 19, 20, 21, 22, 23, 24, 25, 26, 27, 28, 29, 30, 31, 32, 33, 34, 35, 36, 37, 38, 39, 40

## 09 18 540 7329
designator P?
Flat Cable Connector (IDC), Standard Male Header, Straight Press-in Pin, 40 Contacts, Performance Level 3; PCB_Layout: Complies with manufacturer's recommendation.; DrillSize: Corresponds to nominal value.
footprint 918540x329 (Connector; IDC, Straight Press-in Pin, Thru-Hole; 40 Position; Vertical; Pitch 2.54 mm; Body 58.42 x 9.2 x 9.45 mm (LxWxH))
pins: 1, 2, 3, 4, 5, 6, 7, 8, 9, 10, 11, 12, 13, 14, 15, 16, 17, 18, 19, 20, 21, 22, 23, 24, 25, 26, 27, 28, 29, 30, 31, 32, 33, 34, 35, 36, 37, 38, 39, 40

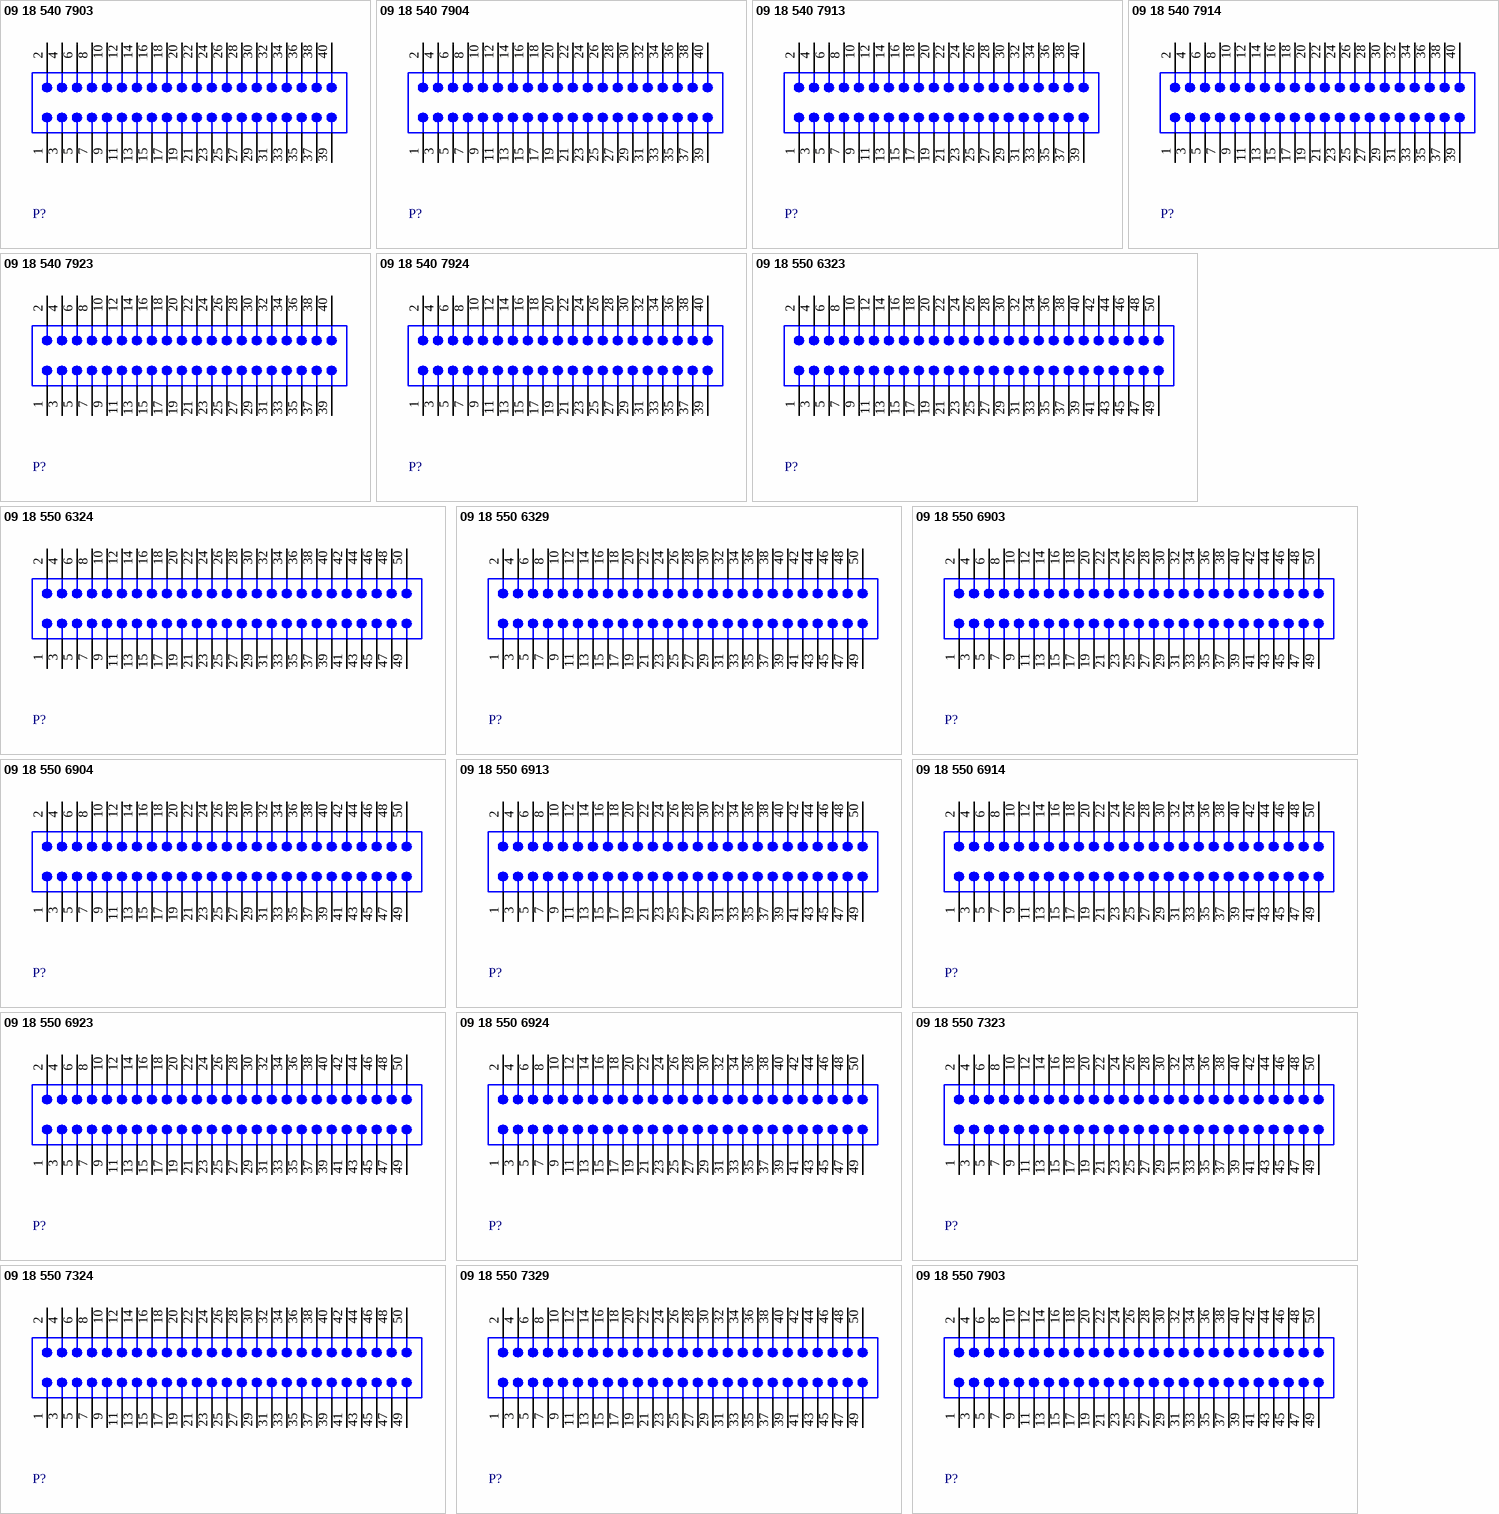
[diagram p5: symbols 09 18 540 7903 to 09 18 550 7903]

## 09 18 540 7903
designator P?
Flat Cable Connector (IDC), Standard Male Header, Angled Solder Pin, 40 Contacts, Long Levers, Performance Level 3; PCB_Layout: Complies with manufacturer's recommendation.; DrillSize: Corresponds to nominal value.
footprint 918540x903 (Connector; IDC, Thru-Hole; 40 Position; Right Angle; Pitch 2.54 mm; Body 70.40 x 8.5 x 25.75 mm (LxHxW), Locking levers)
pins: 1, 2, 3, 4, 5, 6, 7, 8, 9, 10, 11, 12, 13, 14, 15, 16, 17, 18, 19, 20, 21, 22, 23, 24, 25, 26, 27, 28, 29, 30, 31, 32, 33, 34, 35, 36, 37, 38, 39, 40

## 09 18 540 7904
designator P?
Flat Cable Connector (IDC), Standard Male Header, Straight Solder Pin, 40 Contacts, Long Levers, Performance Level 3; PCB_Layout: Complies with manufacturer's recommendation.; DrillSize: Corresponds to nominal value.
footprint 918540x904 (Connector; IDC, Thru-Hole; 40 Position; Vertical; Pitch 2.54 mm; Body 70.40 x 8.5 x 25.75 mm (LxWxH), Locking levers)
pins: 1, 2, 3, 4, 5, 6, 7, 8, 9, 10, 11, 12, 13, 14, 15, 16, 17, 18, 19, 20, 21, 22, 23, 24, 25, 26, 27, 28, 29, 30, 31, 32, 33, 34, 35, 36, 37, 38, 39, 40

## 09 18 540 7913
designator P?
Flat Cable Connector (IDC), Standard Male Header, Angled Solder Pin, 40 Contacts, Short Levers, Performance Level 3; PCB_Layout: Complies with manufacturer's recommendation.; DrillSize: Corresponds to nominal value.
footprint 918540x913 (Connector; IDC, Thru-Hole; 40 Position; Right Angle; Pitch 2.54 mm; Body 70.40 x 8.5 x 23.30 mm (LxHxW), Locking levers)
pins: 1, 2, 3, 4, 5, 6, 7, 8, 9, 10, 11, 12, 13, 14, 15, 16, 17, 18, 19, 20, 21, 22, 23, 24, 25, 26, 27, 28, 29, 30, 31, 32, 33, 34, 35, 36, 37, 38, 39, 40

## 09 18 540 7914
designator P?
Flat Cable Connector (IDC), Standard Male Header, Straight Solder Pin, 40 Contacts, Short Levers, Performance Level 3; PCB_Layout: Complies with manufacturer's recommendation.; DrillSize: Corresponds to nominal value.
footprint 918540x914 (Connector; IDC, Thru-Hole; 40 Position; Vertical; Pitch 2.54 mm; Body 70.40 x 8.5 x 23.30 mm (LxWxH), Locking levers)
pins: 1, 2, 3, 4, 5, 6, 7, 8, 9, 10, 11, 12, 13, 14, 15, 16, 17, 18, 19, 20, 21, 22, 23, 24, 25, 26, 27, 28, 29, 30, 31, 32, 33, 34, 35, 36, 37, 38, 39, 40

## 09 18 540 7923
designator P?
Flat Cable Connector (IDC), Standard Male Header, Angled Solder Pin, 40 Contacts, Without Levers, Performance Level 3; PCB_Layout: Complies with manufacturer's recommendation.; DrillSize: Corresponds to nominal value.
footprint 918540x923 (Connector; IDC, Thru-Hole; 40 Position; Right Angle; Pitch 2.54 mm; Body 70.40 x 8.5 x 17.30 mm (LxHxW), Without locking levers)
pins: 1, 2, 3, 4, 5, 6, 7, 8, 9, 10, 11, 12, 13, 14, 15, 16, 17, 18, 19, 20, 21, 22, 23, 24, 25, 26, 27, 28, 29, 30, 31, 32, 33, 34, 35, 36, 37, 38, 39, 40

## 09 18 540 7924
designator P?
Flat Cable Connector (IDC), Standard Male Header, Straight Solder Pin, 40 Contacts, Without Levers, Performance Level 3; PCB_Layout: Complies with manufacturer's recommendation.; DrillSize: Corresponds to nominal value.
footprint 918540x924 (Connector; IDC, Thru-Hole; 40 Position; Vertical; Pitch 2.54 mm; Body 70.40 x 8.5 x 17.30 mm (LxWxH), Without locking levers)
pins: 1, 2, 3, 4, 5, 6, 7, 8, 9, 10, 11, 12, 13, 14, 15, 16, 17, 18, 19, 20, 21, 22, 23, 24, 25, 26, 27, 28, 29, 30, 31, 32, 33, 34, 35, 36, 37, 38, 39, 40

## 09 18 550 6323
designator P?
Flat Cable Connector (IDC), Low-Profile Male Header, Angled Solder Pin, 50 Contacts, Performance Level 2; PCB_Layout: Complies with manufacturer's recommendation.; DrillSize: Corresponds to nominal value.
footprint 918550x323 (Connector; IDC, Low Profile Male Header, Thru-Hole; 50 Position; Right Angle; Pitch 2.54 mm; Body 71.32 x 8.9 x 9.2 mm (LxWxH))
pins: 1, 2, 3, 4, 5, 6, 7, 8, 9, 10, 11, 12, 13, 14, 15, 16, 17, 18, 19, 20, 21, 22, 23, 24, 25, 26, 27, 28, 29, 30, 31, 32, 33, 34, 35, 36, 37, 38, 39, 40, 41, 42, 43, 44, 45, 46, 47, 48, 49, 50

## 09 18 550 6324
designator P?
Flat Cable Connector (IDC), Low-Profile Male Header, Straight Solder Pin, 50 Contacts, Performance Level 2; PCB_Layout: Complies with manufacturer's recommendation.; DrillSize: Corresponds to nominal value.
footprint 918550x324 (Connector; IDC, Low Profile Male Header, Thru-Hole; 50 Position; Vertical; Pitch 2.54 mm; Body 71.32 x 9.2 x 9.45 mm (LxWxH))
pins: 1, 2, 3, 4, 5, 6, 7, 8, 9, 10, 11, 12, 13, 14, 15, 16, 17, 18, 19, 20, 21, 22, 23, 24, 25, 26, 27, 28, 29, 30, 31, 32, 33, 34, 35, 36, 37, 38, 39, 40, 41, 42, 43, 44, 45, 46, 47, 48, 49, 50

## 09 18 550 6329
designator P?
Flat Cable Connector (IDC), Standard Male Header, Straight Press-in Pin, 50 Contacts, Performance Level 2; PCB_Layout: Complies with manufacturer's recommendation.; DrillSize: Corresponds to nominal value.
footprint 918550x329 (Connector; IDC, Straight Press-in Pin, Thru-Hole; 50 Position; Vertical; Pitch 2.54 mm; Body 71.32 x 9.2 x 9.45 mm (LxWxH))
pins: 1, 2, 3, 4, 5, 6, 7, 8, 9, 10, 11, 12, 13, 14, 15, 16, 17, 18, 19, 20, 21, 22, 23, 24, 25, 26, 27, 28, 29, 30, 31, 32, 33, 34, 35, 36, 37, 38, 39, 40, 41, 42, 43, 44, 45, 46, 47, 48, 49, 50

## 09 18 550 6903
designator P?
Flat Cable Connector (IDC), Standard Male Header, Angled Solder Pin, 50 Contacts, Long Levers, Performance Level 2; PCB_Layout: Complies with manufacturer's recommendation.; DrillSize: Corresponds to nominal value.
footprint 918550x903 (Connector; IDC, Thru-Hole; 50 Position; Right Angle; Pitch 2.54 mm; Body 83.10 x 8.5 x 25.75 mm (LxHxW), Locking levers)
pins: 1, 2, 3, 4, 5, 6, 7, 8, 9, 10, 11, 12, 13, 14, 15, 16, 17, 18, 19, 20, 21, 22, 23, 24, 25, 26, 27, 28, 29, 30, 31, 32, 33, 34, 35, 36, 37, 38, 39, 40, 41, 42, 43, 44, 45, 46, 47, 48, 49, 50

## 09 18 550 6904
designator P?
Flat Cable Connector (IDC), Standard Male Header, Straight Solder Pin, 50 Contacts, Long Levers, Performance Level 2; PCB_Layout: Complies with manufacturer's recommendation.; DrillSize: Corresponds to nominal value.
footprint 918550x904 (Connector; IDC, Thru-Hole; 50 Position; Vertical; Pitch 2.54 mm; Body 83.10 x 8.5 x 25.75 mm (LxWxH), Locking levers)
pins: 1, 2, 3, 4, 5, 6, 7, 8, 9, 10, 11, 12, 13, 14, 15, 16, 17, 18, 19, 20, 21, 22, 23, 24, 25, 26, 27, 28, 29, 30, 31, 32, 33, 34, 35, 36, 37, 38, 39, 40, 41, 42, 43, 44, 45, 46, 47, 48, 49, 50

## 09 18 550 6913
designator P?
Flat Cable Connector (IDC), Standard Male Header, Angled Solder Pin, 50 Contacts, Short Levers, Performance Level 2; PCB_Layout: Complies with manufacturer's recommendation.; DrillSize: Corresponds to nominal value.
footprint 918550x913 (Connector; IDC, Thru-Hole; 50 Position; Right Angle; Pitch 2.54 mm; Body 83.10 x 8.5 x 23.30 mm (LxHxW), Locking levers)
pins: 1, 2, 3, 4, 5, 6, 7, 8, 9, 10, 11, 12, 13, 14, 15, 16, 17, 18, 19, 20, 21, 22, 23, 24, 25, 26, 27, 28, 29, 30, 31, 32, 33, 34, 35, 36, 37, 38, 39, 40, 41, 42, 43, 44, 45, 46, 47, 48, 49, 50

## 09 18 550 6914
designator P?
Flat Cable Connector (IDC), Standard Male Header, Straight Solder Pin, 50 Contacts, Short Levers, Performance Level 2; PCB_Layout: Complies with manufacturer's recommendation.; DrillSize: Corresponds to nominal value.
footprint 918550x914 (Connector; IDC, Thru-Hole; 50 Position; Vertical; Pitch 2.54 mm; Body 83.10 x 8.5 x 23.30 mm (LxWxH), Locking levers)
pins: 1, 2, 3, 4, 5, 6, 7, 8, 9, 10, 11, 12, 13, 14, 15, 16, 17, 18, 19, 20, 21, 22, 23, 24, 25, 26, 27, 28, 29, 30, 31, 32, 33, 34, 35, 36, 37, 38, 39, 40, 41, 42, 43, 44, 45, 46, 47, 48, 49, 50

## 09 18 550 6923
designator P?
Flat Cable Connector (IDC), Standard Male Header, Angled Solder Pin, 50 Contacts, Without Levers, Performance Level 2; PCB_Layout: Complies with manufacturer's recommendation.; DrillSize: Corresponds to nominal value.
footprint 918550x923 (Connector; IDC, Thru-Hole; 50 Position; Right Angle; Pitch 2.54 mm; Body 83.10 x 8.5 x 17.30 mm (LxHxW), Without locking levers)
pins: 1, 2, 3, 4, 5, 6, 7, 8, 9, 10, 11, 12, 13, 14, 15, 16, 17, 18, 19, 20, 21, 22, 23, 24, 25, 26, 27, 28, 29, 30, 31, 32, 33, 34, 35, 36, 37, 38, 39, 40, 41, 42, 43, 44, 45, 46, 47, 48, 49, 50

## 09 18 550 6924
designator P?
Flat Cable Connector (IDC), Standard Male Header, Straight Solder Pin, 50 Contacts, Without Levers, Performance Level 2; PCB_Layout: Complies with manufacturer's recommendation.; DrillSize: Corresponds to nominal value.
footprint 918550x924 (Connector; IDC, Thru-Hole; 50 Position; Vertical; Pitch 2.54 mm; Body 83.10 x 8.5 x 17.30 mm (LxWxH), Without locking levers)
pins: 1, 2, 3, 4, 5, 6, 7, 8, 9, 10, 11, 12, 13, 14, 15, 16, 17, 18, 19, 20, 21, 22, 23, 24, 25, 26, 27, 28, 29, 30, 31, 32, 33, 34, 35, 36, 37, 38, 39, 40, 41, 42, 43, 44, 45, 46, 47, 48, 49, 50

## 09 18 550 7323
designator P?
Flat Cable Connector (IDC), Low-Profile Male Header, Angled Solder Pin, 50 Contacts, Performance Level 3; PCB_Layout: Complies with manufacturer's recommendation.; DrillSize: Corresponds to nominal value.
footprint 918550x323 (Connector; IDC, Low Profile Male Header, Thru-Hole; 50 Position; Right Angle; Pitch 2.54 mm; Body 71.32 x 8.9 x 9.2 mm (LxWxH))
pins: 1, 2, 3, 4, 5, 6, 7, 8, 9, 10, 11, 12, 13, 14, 15, 16, 17, 18, 19, 20, 21, 22, 23, 24, 25, 26, 27, 28, 29, 30, 31, 32, 33, 34, 35, 36, 37, 38, 39, 40, 41, 42, 43, 44, 45, 46, 47, 48, 49, 50

## 09 18 550 7324
designator P?
Flat Cable Connector (IDC), Low-Profile Male Header, Straight Solder Pin, 50 Contacts, Performance Level 3; PCB_Layout: Complies with manufacturer's recommendation.; DrillSize: Corresponds to nominal value.
footprint 918550x324 (Connector; IDC, Low Profile Male Header, Thru-Hole; 50 Position; Vertical; Pitch 2.54 mm; Body 71.32 x 9.2 x 9.45 mm (LxWxH))
pins: 1, 2, 3, 4, 5, 6, 7, 8, 9, 10, 11, 12, 13, 14, 15, 16, 17, 18, 19, 20, 21, 22, 23, 24, 25, 26, 27, 28, 29, 30, 31, 32, 33, 34, 35, 36, 37, 38, 39, 40, 41, 42, 43, 44, 45, 46, 47, 48, 49, 50

## 09 18 550 7329
designator P?
Flat Cable Connector (IDC), Standard Male Header, Straight Press-in Pin, 50 Contacts, Performance Level 3; PCB_Layout: Complies with manufacturer's recommendation.; DrillSize: Corresponds to nominal value.
footprint 918550x329 (Connector; IDC, Straight Press-in Pin, Thru-Hole; 50 Position; Vertical; Pitch 2.54 mm; Body 71.32 x 9.2 x 9.45 mm (LxWxH))
pins: 1, 2, 3, 4, 5, 6, 7, 8, 9, 10, 11, 12, 13, 14, 15, 16, 17, 18, 19, 20, 21, 22, 23, 24, 25, 26, 27, 28, 29, 30, 31, 32, 33, 34, 35, 36, 37, 38, 39, 40, 41, 42, 43, 44, 45, 46, 47, 48, 49, 50

## 09 18 550 7903
designator P?
Flat Cable Connector (IDC), Standard Male Header, Angled Solder Pin, 50 Contacts, Long Levers, Performance Level 3; PCB_Layout: Complies with manufacturer's recommendation.; DrillSize: Corresponds to nominal value.
footprint 918550x903 (Connector; IDC, Thru-Hole; 50 Position; Right Angle; Pitch 2.54 mm; Body 83.10 x 8.5 x 25.75 mm (LxHxW), Locking levers)
pins: 1, 2, 3, 4, 5, 6, 7, 8, 9, 10, 11, 12, 13, 14, 15, 16, 17, 18, 19, 20, 21, 22, 23, 24, 25, 26, 27, 28, 29, 30, 31, 32, 33, 34, 35, 36, 37, 38, 39, 40, 41, 42, 43, 44, 45, 46, 47, 48, 49, 50

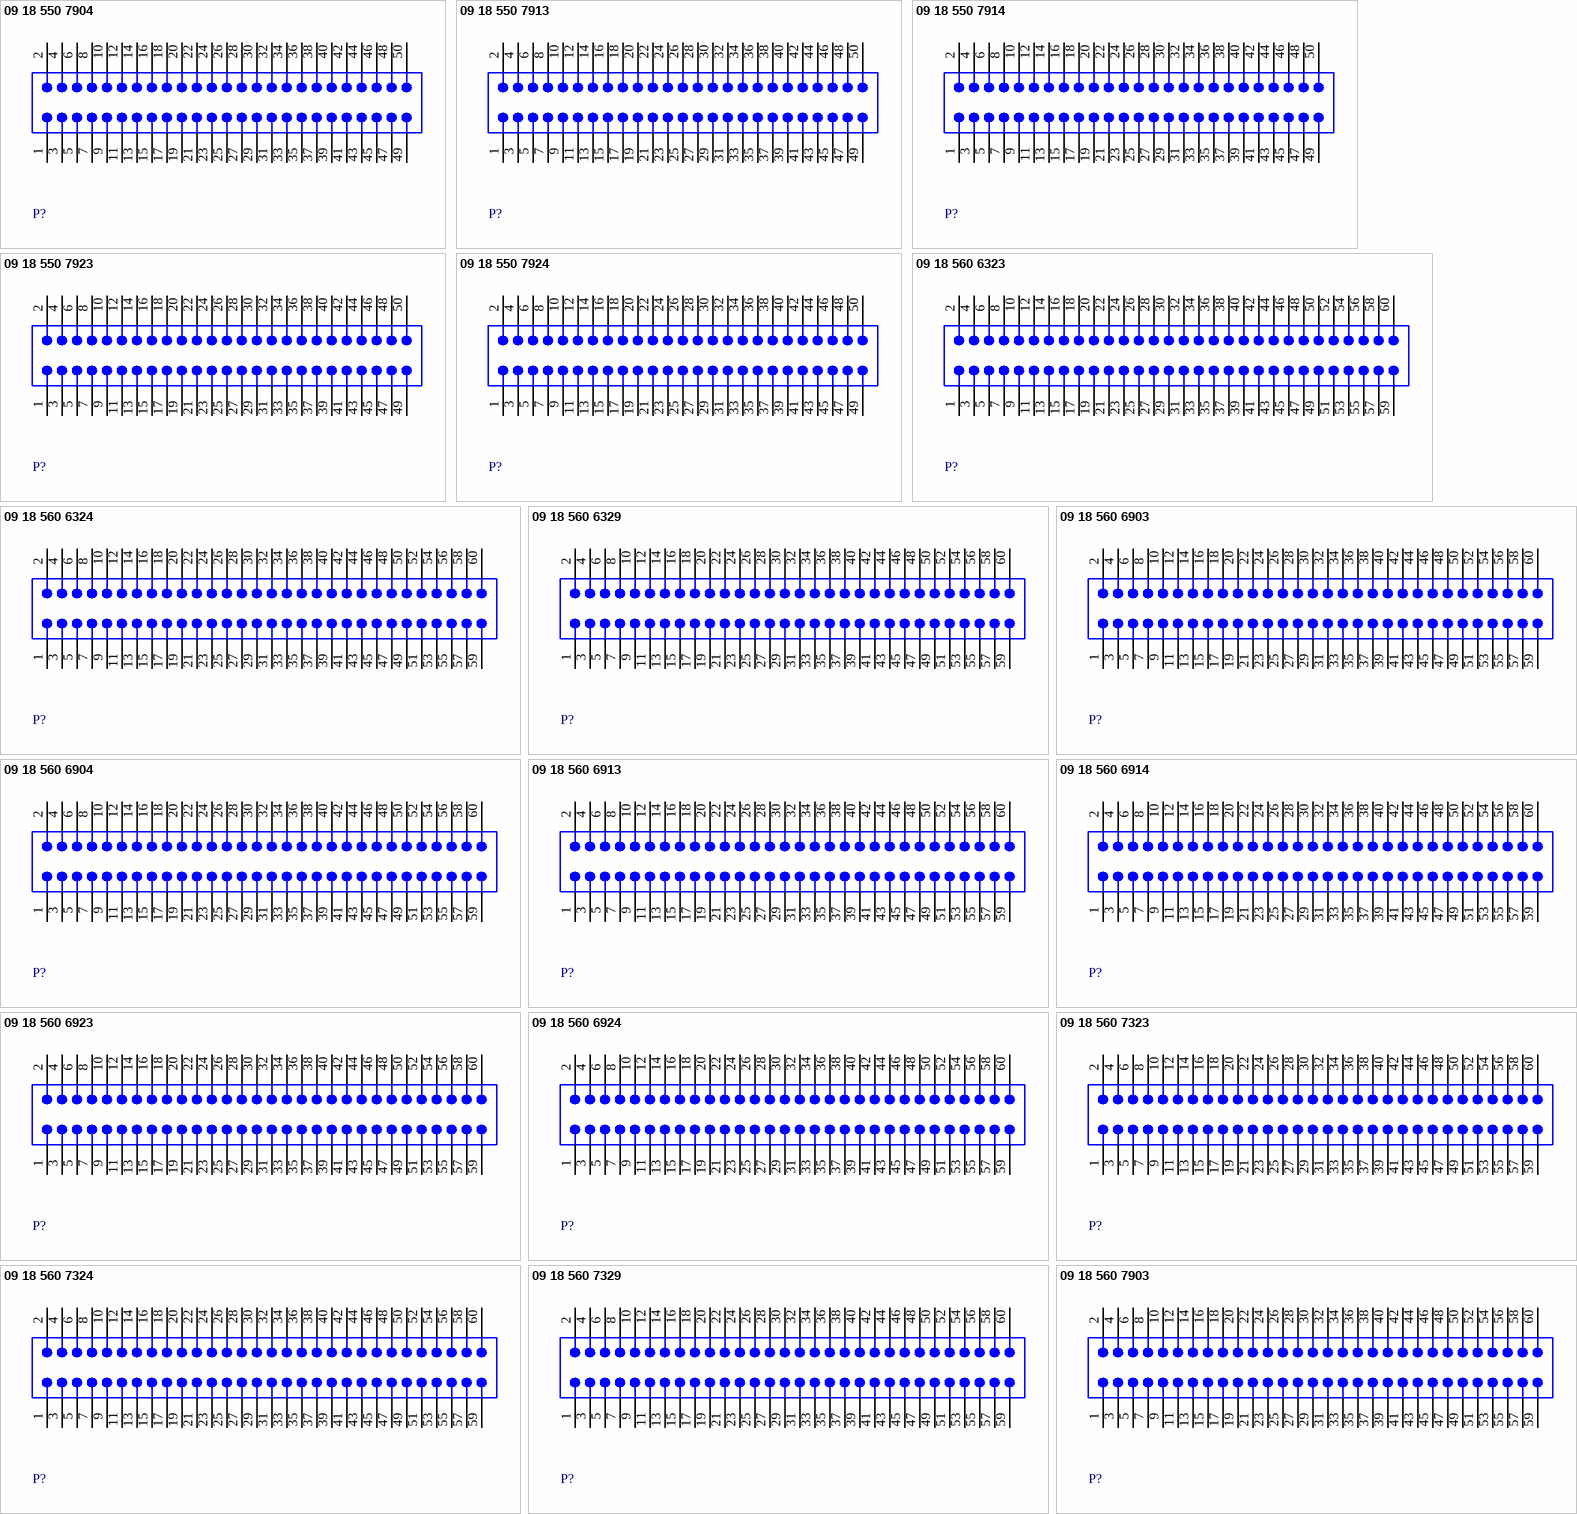
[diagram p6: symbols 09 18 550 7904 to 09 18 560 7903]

## 09 18 550 7904
designator P?
Flat Cable Connector (IDC), Standard Male Header, Straight Solder Pin, 50 Contacts, Long Levers, Performance Level 3; PCB_Layout: Complies with manufacturer's recommendation.; DrillSize: Corresponds to nominal value.
footprint 918550x904 (Connector; IDC, Thru-Hole; 50 Position; Vertical; Pitch 2.54 mm; Body 83.10 x 8.5 x 25.75 mm (LxWxH), Locking levers)
pins: 1, 2, 3, 4, 5, 6, 7, 8, 9, 10, 11, 12, 13, 14, 15, 16, 17, 18, 19, 20, 21, 22, 23, 24, 25, 26, 27, 28, 29, 30, 31, 32, 33, 34, 35, 36, 37, 38, 39, 40, 41, 42, 43, 44, 45, 46, 47, 48, 49, 50

## 09 18 550 7913
designator P?
Flat Cable Connector (IDC), Standard Male Header, Angled Solder Pin, 50 Contacts, Short Levers, Performance Level 3; PCB_Layout: Complies with manufacturer's recommendation.; DrillSize: Corresponds to nominal value.
footprint 918550x913 (Connector; IDC, Thru-Hole; 50 Position; Right Angle; Pitch 2.54 mm; Body 83.10 x 8.5 x 23.30 mm (LxHxW), Locking levers)
pins: 1, 2, 3, 4, 5, 6, 7, 8, 9, 10, 11, 12, 13, 14, 15, 16, 17, 18, 19, 20, 21, 22, 23, 24, 25, 26, 27, 28, 29, 30, 31, 32, 33, 34, 35, 36, 37, 38, 39, 40, 41, 42, 43, 44, 45, 46, 47, 48, 49, 50

## 09 18 550 7914
designator P?
Flat Cable Connector (IDC), Standard Male Header, Straight Solder Pin, 50 Contacts, Short Levers, Performance Level 3; PCB_Layout: Complies with manufacturer's recommendation.; DrillSize: Corresponds to nominal value.
footprint 918550x914 (Connector; IDC, Thru-Hole; 50 Position; Vertical; Pitch 2.54 mm; Body 83.10 x 8.5 x 23.30 mm (LxWxH), Locking levers)
pins: 1, 2, 3, 4, 5, 6, 7, 8, 9, 10, 11, 12, 13, 14, 15, 16, 17, 18, 19, 20, 21, 22, 23, 24, 25, 26, 27, 28, 29, 30, 31, 32, 33, 34, 35, 36, 37, 38, 39, 40, 41, 42, 43, 44, 45, 46, 47, 48, 49, 50

## 09 18 550 7923
designator P?
Flat Cable Connector (IDC), Standard Male Header, Angled Solder Pin, 50 Contacts, Without Levers, Performance Level 3; PCB_Layout: Complies with manufacturer's recommendation.; DrillSize: Corresponds to nominal value.
footprint 918550x923 (Connector; IDC, Thru-Hole; 50 Position; Right Angle; Pitch 2.54 mm; Body 83.10 x 8.5 x 17.30 mm (LxHxW), Without locking levers)
pins: 1, 2, 3, 4, 5, 6, 7, 8, 9, 10, 11, 12, 13, 14, 15, 16, 17, 18, 19, 20, 21, 22, 23, 24, 25, 26, 27, 28, 29, 30, 31, 32, 33, 34, 35, 36, 37, 38, 39, 40, 41, 42, 43, 44, 45, 46, 47, 48, 49, 50

## 09 18 550 7924
designator P?
Flat Cable Connector (IDC), Standard Male Header, Straight Solder Pin, 50 Contacts, Without Levers, Performance Level 3; PCB_Layout: Complies with manufacturer's recommendation.; DrillSize: Corresponds to nominal value.
footprint 918550x924 (Connector; IDC, Thru-Hole; 50 Position; Vertical; Pitch 2.54 mm; Body 83.10 x 8.5 x 17.30 mm (LxWxH), Without locking levers)
pins: 1, 2, 3, 4, 5, 6, 7, 8, 9, 10, 11, 12, 13, 14, 15, 16, 17, 18, 19, 20, 21, 22, 23, 24, 25, 26, 27, 28, 29, 30, 31, 32, 33, 34, 35, 36, 37, 38, 39, 40, 41, 42, 43, 44, 45, 46, 47, 48, 49, 50

## 09 18 560 6323
designator P?
Flat Cable Connector (IDC), Low-Profile Male Header, Angled Solder Pin, 60 Contacts, Performance Level 2; PCB_Layout: Complies with manufacturer's recommendation.; DrillSize: Corresponds to nominal value.
footprint 918560x323 (Connector; IDC, Low Profile Male Header, Thru-Hole; 60 Position; Right Angle; Pitch 2.54 mm; Body 84.02 x 8.9 x 9.2 mm (LxWxH))
pins: 1, 2, 3, 4, 5, 6, 7, 8, 9, 10, 11, 12, 13, 14, 15, 16, 17, 18, 19, 20, 21, 22, 23, 24, 25, 26, 27, 28, 29, 30, 31, 32, 33, 34, 35, 36, 37, 38, 39, 40, 41, 42, 43, 44, 45, 46, 47, 48, 49, 50, 51, 52, 53, 54, 55, 56, 57, 58, 59, 60

## 09 18 560 6324
designator P?
Flat Cable Connector (IDC), Low-Profile Male Header, Straight Solder Pin, 60 Contacts, Performance Level 2; PCB_Layout: Complies with manufacturer's recommendation.; DrillSize: Corresponds to nominal value.
footprint 918560x324 (Connector; IDC, Low Profile Male Header, Thru-Hole; 60 Position; Vertical; Pitch 2.54 mm; Body 84.02 x 9.2 x 9.45 mm (LxWxH))
pins: 1, 2, 3, 4, 5, 6, 7, 8, 9, 10, 11, 12, 13, 14, 15, 16, 17, 18, 19, 20, 21, 22, 23, 24, 25, 26, 27, 28, 29, 30, 31, 32, 33, 34, 35, 36, 37, 38, 39, 40, 41, 42, 43, 44, 45, 46, 47, 48, 49, 50, 51, 52, 53, 54, 55, 56, 57, 58, 59, 60

## 09 18 560 6329
designator P?
Flat Cable Connector (IDC), Standard Male Header, Straight Press-in Pin, 60 Contacts, Performance Level 2; PCB_Layout: Complies with manufacturer's recommendation.; DrillSize: Corresponds to nominal value.
footprint 918560x329 (Connector; IDC, Straight Press-in Pin, Thru-Hole; 60 Position; Vertical; Pitch 2.54 mm; Body 84.02 x 9.2 x 9.45 mm (LxWxH))
pins: 1, 2, 3, 4, 5, 6, 7, 8, 9, 10, 11, 12, 13, 14, 15, 16, 17, 18, 19, 20, 21, 22, 23, 24, 25, 26, 27, 28, 29, 30, 31, 32, 33, 34, 35, 36, 37, 38, 39, 40, 41, 42, 43, 44, 45, 46, 47, 48, 49, 50, 51, 52, 53, 54, 55, 56, 57, 58, 59, 60

## 09 18 560 6903
designator P?
Flat Cable Connector (IDC), Standard Male Header, Angled Solder Pin, 60 Contacts, Long Levers, Performance Level 2; PCB_Layout: Complies with manufacturer's recommendation.; DrillSize: Corresponds to nominal value.
footprint 918560x903 (Connector; IDC, Thru-Hole; 60 Position; Right Angle; Pitch 2.54 mm; Body 95.80 x 8.5 x 25.75 mm (LxHxW), Locking levers)
pins: 1, 2, 3, 4, 5, 6, 7, 8, 9, 10, 11, 12, 13, 14, 15, 16, 17, 18, 19, 20, 21, 22, 23, 24, 25, 26, 27, 28, 29, 30, 31, 32, 33, 34, 35, 36, 37, 38, 39, 40, 41, 42, 43, 44, 45, 46, 47, 48, 49, 50, 51, 52, 53, 54, 55, 56, 57, 58, 59, 60

## 09 18 560 6904
designator P?
Flat Cable Connector (IDC), Standard Male Header, Straight Solder Pin, 60 Contacts, Long Levers, Performance Level 2; PCB_Layout: Complies with manufacturer's recommendation.; DrillSize: Corresponds to nominal value.
footprint 918560x904 (Connector; IDC, Thru-Hole; 60 Position; Vertical; Pitch 2.54 mm; Body 95.80 x 8.5 x 25.75 mm (LxWxH), Locking levers)
pins: 1, 2, 3, 4, 5, 6, 7, 8, 9, 10, 11, 12, 13, 14, 15, 16, 17, 18, 19, 20, 21, 22, 23, 24, 25, 26, 27, 28, 29, 30, 31, 32, 33, 34, 35, 36, 37, 38, 39, 40, 41, 42, 43, 44, 45, 46, 47, 48, 49, 50, 51, 52, 53, 54, 55, 56, 57, 58, 59, 60

## 09 18 560 6913
designator P?
Flat Cable Connector (IDC), Standard Male Header, Angled Solder Pin, 60 Contacts, Short Levers, Performance Level 2; PCB_Layout: Complies with manufacturer's recommendation.; DrillSize: Corresponds to nominal value.
footprint 918560x913 (Connector; IDC, Thru-Hole; 60 Position; Right Angle; Pitch 2.54 mm; Body 95.80 x 8.5 x 23.30 mm (LxHxW), Locking levers)
pins: 1, 2, 3, 4, 5, 6, 7, 8, 9, 10, 11, 12, 13, 14, 15, 16, 17, 18, 19, 20, 21, 22, 23, 24, 25, 26, 27, 28, 29, 30, 31, 32, 33, 34, 35, 36, 37, 38, 39, 40, 41, 42, 43, 44, 45, 46, 47, 48, 49, 50, 51, 52, 53, 54, 55, 56, 57, 58, 59, 60

## 09 18 560 6914
designator P?
Flat Cable Connector (IDC), Standard Male Header, Straight Solder Pin, 60 Contacts, Short Levers, Performance Level 2; PCB_Layout: Complies with manufacturer's recommendation.; DrillSize: Corresponds to nominal value.
footprint 918560x914 (Connector; IDC, Thru-Hole; 60 Position; Vertical; Pitch 2.54 mm; Body 95.80 x 8.5 x 23.30 mm (LxWxH), Locking levers)
pins: 1, 2, 3, 4, 5, 6, 7, 8, 9, 10, 11, 12, 13, 14, 15, 16, 17, 18, 19, 20, 21, 22, 23, 24, 25, 26, 27, 28, 29, 30, 31, 32, 33, 34, 35, 36, 37, 38, 39, 40, 41, 42, 43, 44, 45, 46, 47, 48, 49, 50, 51, 52, 53, 54, 55, 56, 57, 58, 59, 60

## 09 18 560 6923
designator P?
Flat Cable Connector (IDC), Standard Male Header, Angled Solder Pin, 60 Contacts, Without Levers, Performance Level 2; PCB_Layout: Complies with manufacturer's recommendation.; DrillSize: Corresponds to nominal value.
footprint 918560x923 (Connector; IDC, Thru-Hole; 60 Position; Right Angle; Pitch 2.54 mm; Body 95.80 x 8.5 x 17.30 mm (LxHxW), Without locking levers)
pins: 1, 2, 3, 4, 5, 6, 7, 8, 9, 10, 11, 12, 13, 14, 15, 16, 17, 18, 19, 20, 21, 22, 23, 24, 25, 26, 27, 28, 29, 30, 31, 32, 33, 34, 35, 36, 37, 38, 39, 40, 41, 42, 43, 44, 45, 46, 47, 48, 49, 50, 51, 52, 53, 54, 55, 56, 57, 58, 59, 60

## 09 18 560 6924
designator P?
Flat Cable Connector (IDC), Standard Male Header, Straight Solder Pin, 60 Contacts, Without Levers, Performance Level 2; PCB_Layout: Complies with manufacturer's recommendation.; DrillSize: Corresponds to nominal value.
footprint 918560x924 (Connector; IDC, Thru-Hole; 60 Position; Vertical; Pitch 2.54 mm; Body 95.80 x 8.5 x 17.30 mm (LxWxH), Without locking levers)
pins: 1, 2, 3, 4, 5, 6, 7, 8, 9, 10, 11, 12, 13, 14, 15, 16, 17, 18, 19, 20, 21, 22, 23, 24, 25, 26, 27, 28, 29, 30, 31, 32, 33, 34, 35, 36, 37, 38, 39, 40, 41, 42, 43, 44, 45, 46, 47, 48, 49, 50, 51, 52, 53, 54, 55, 56, 57, 58, 59, 60

## 09 18 560 7323
designator P?
Flat Cable Connector (IDC), Low-Profile Male Header, Angled Solder Pin, 60 Contacts, Performance Level 3; PCB_Layout: Complies with manufacturer's recommendation.; DrillSize: Corresponds to nominal value.
footprint 918560x323 (Connector; IDC, Low Profile Male Header, Thru-Hole; 60 Position; Right Angle; Pitch 2.54 mm; Body 84.02 x 8.9 x 9.2 mm (LxWxH))
pins: 1, 2, 3, 4, 5, 6, 7, 8, 9, 10, 11, 12, 13, 14, 15, 16, 17, 18, 19, 20, 21, 22, 23, 24, 25, 26, 27, 28, 29, 30, 31, 32, 33, 34, 35, 36, 37, 38, 39, 40, 41, 42, 43, 44, 45, 46, 47, 48, 49, 50, 51, 52, 53, 54, 55, 56, 57, 58, 59, 60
